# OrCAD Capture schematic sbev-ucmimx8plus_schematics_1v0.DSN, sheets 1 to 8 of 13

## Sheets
1 11. M.2 for WiFi, LEDs: size A3; title: SBEV-UCMIMX8PLUS    11. M.2 for WiFi module; rev: 1.0; note: 8000168001
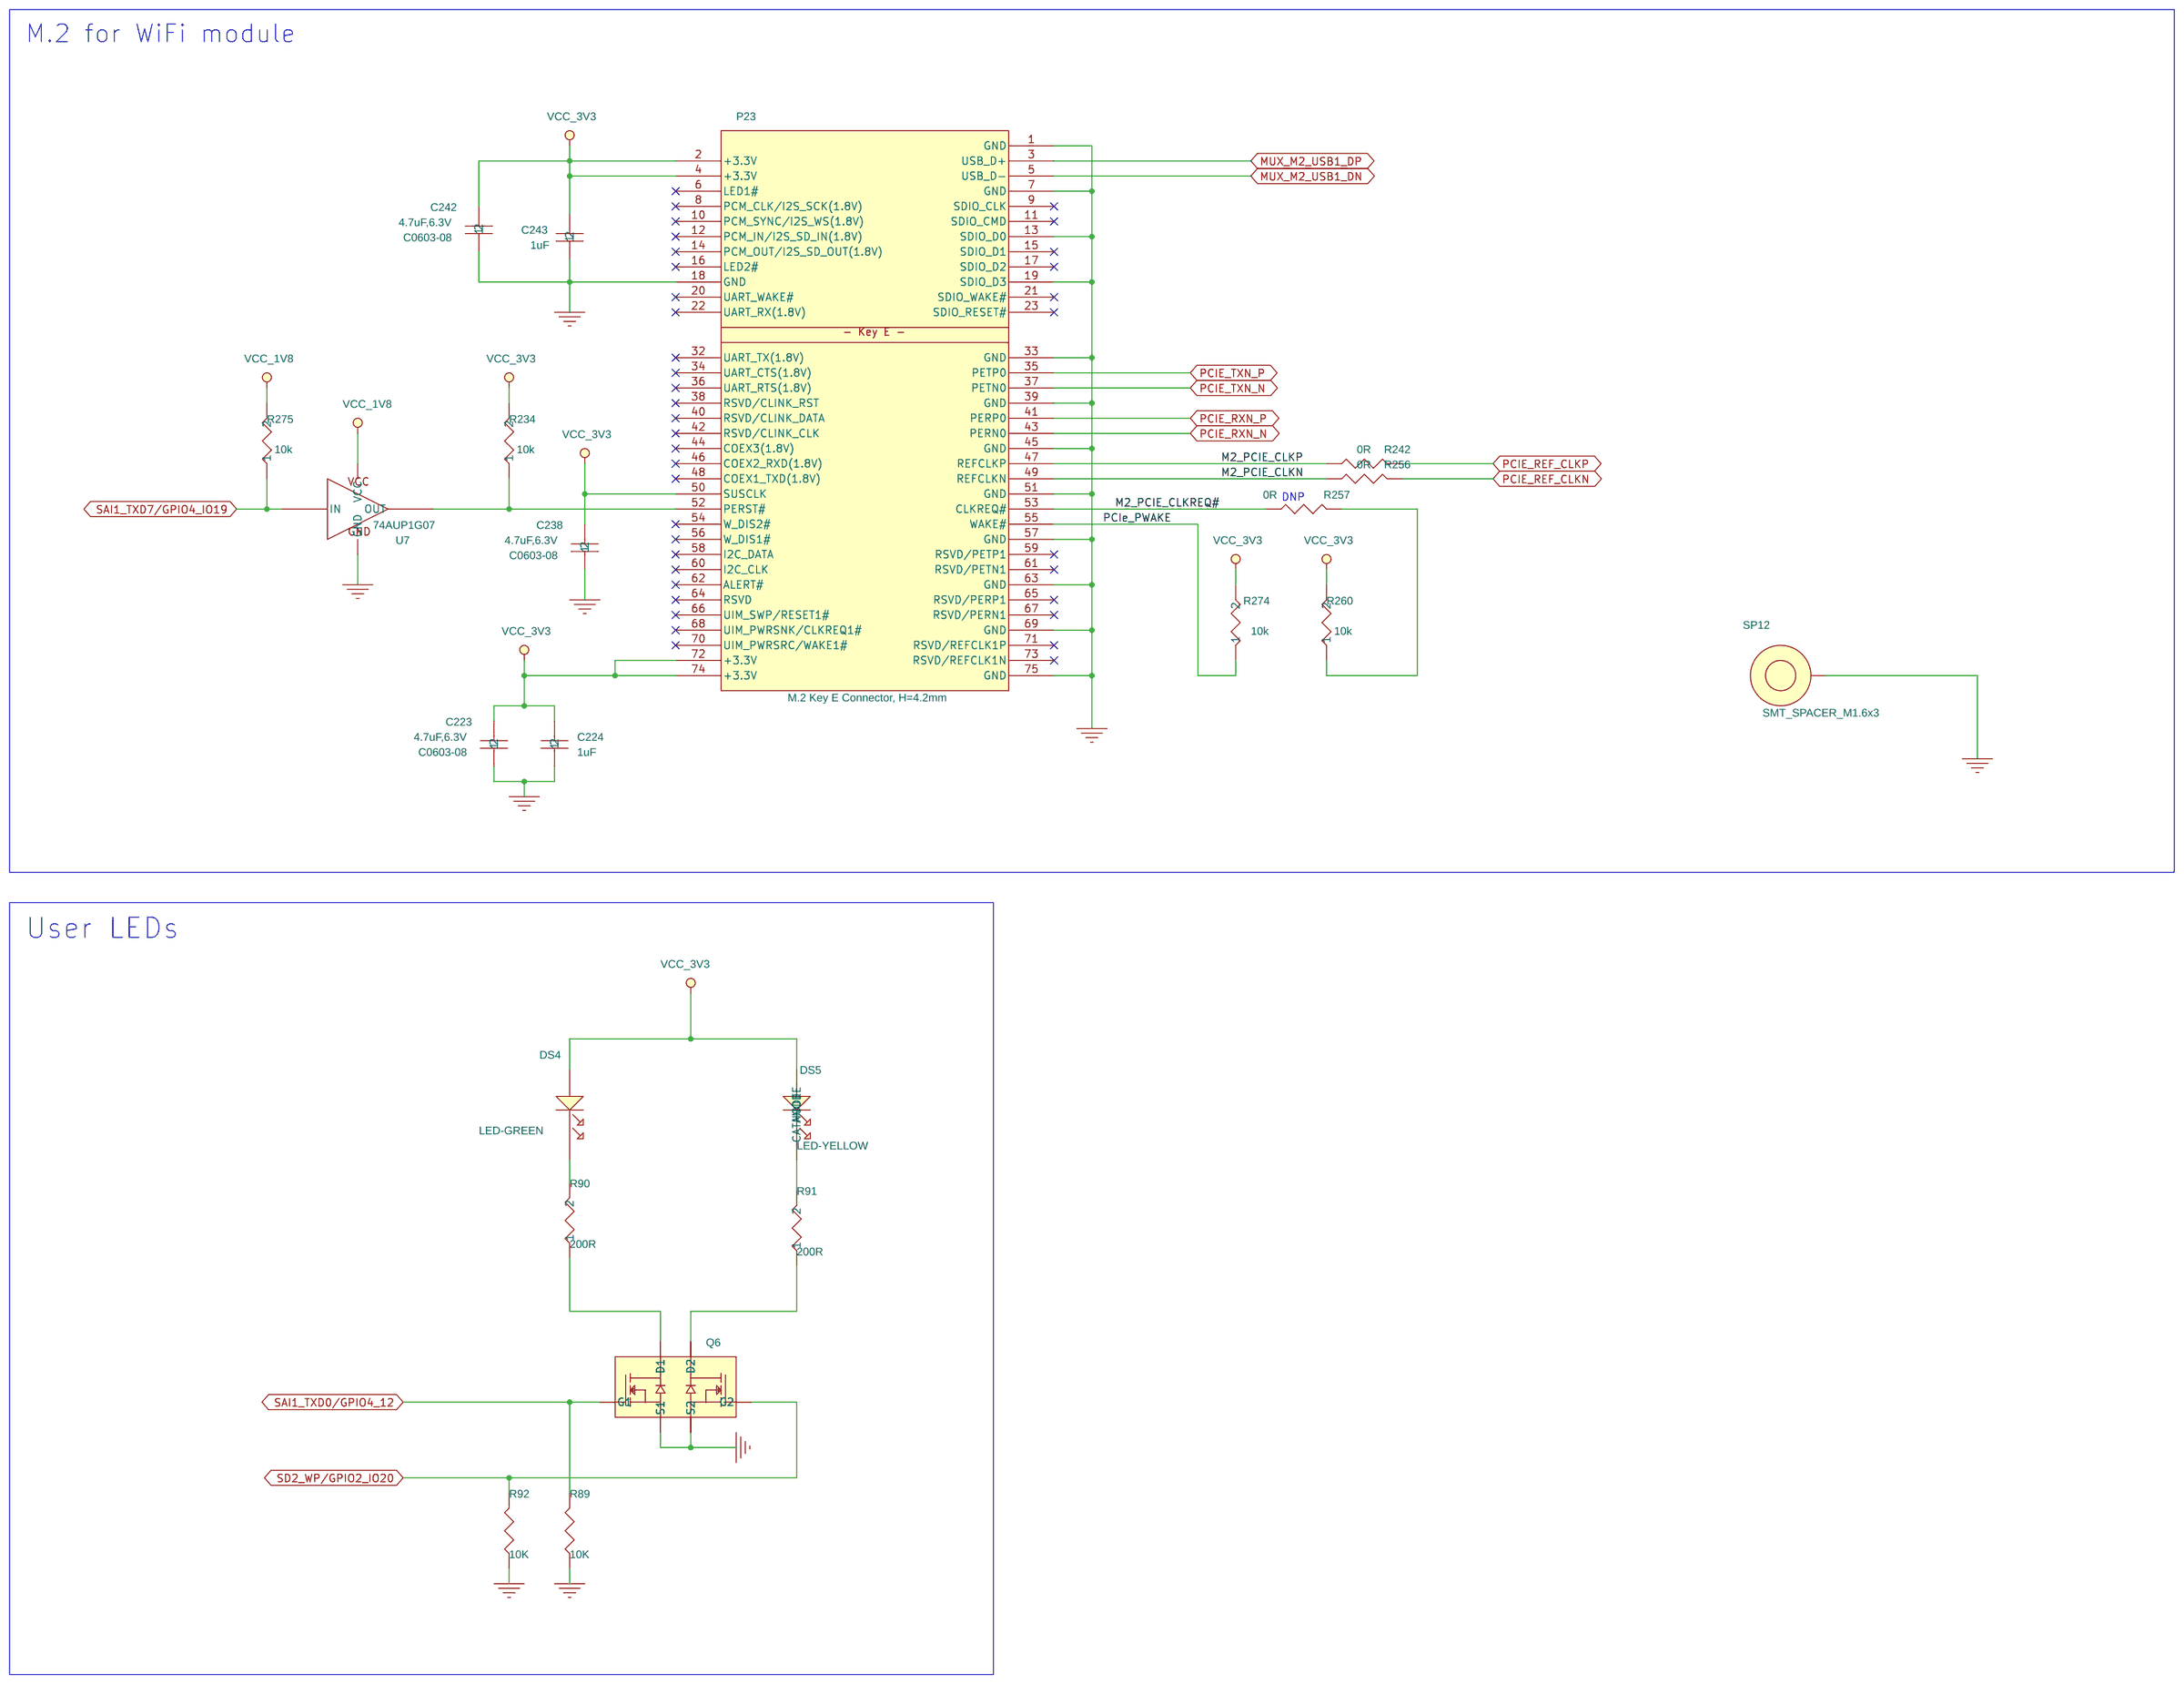
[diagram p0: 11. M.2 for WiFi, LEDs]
2 04. Carrier-board Ethernet: size A3; title: SBEV-UCMIMX8PLUS      04. Secondary Ethernet
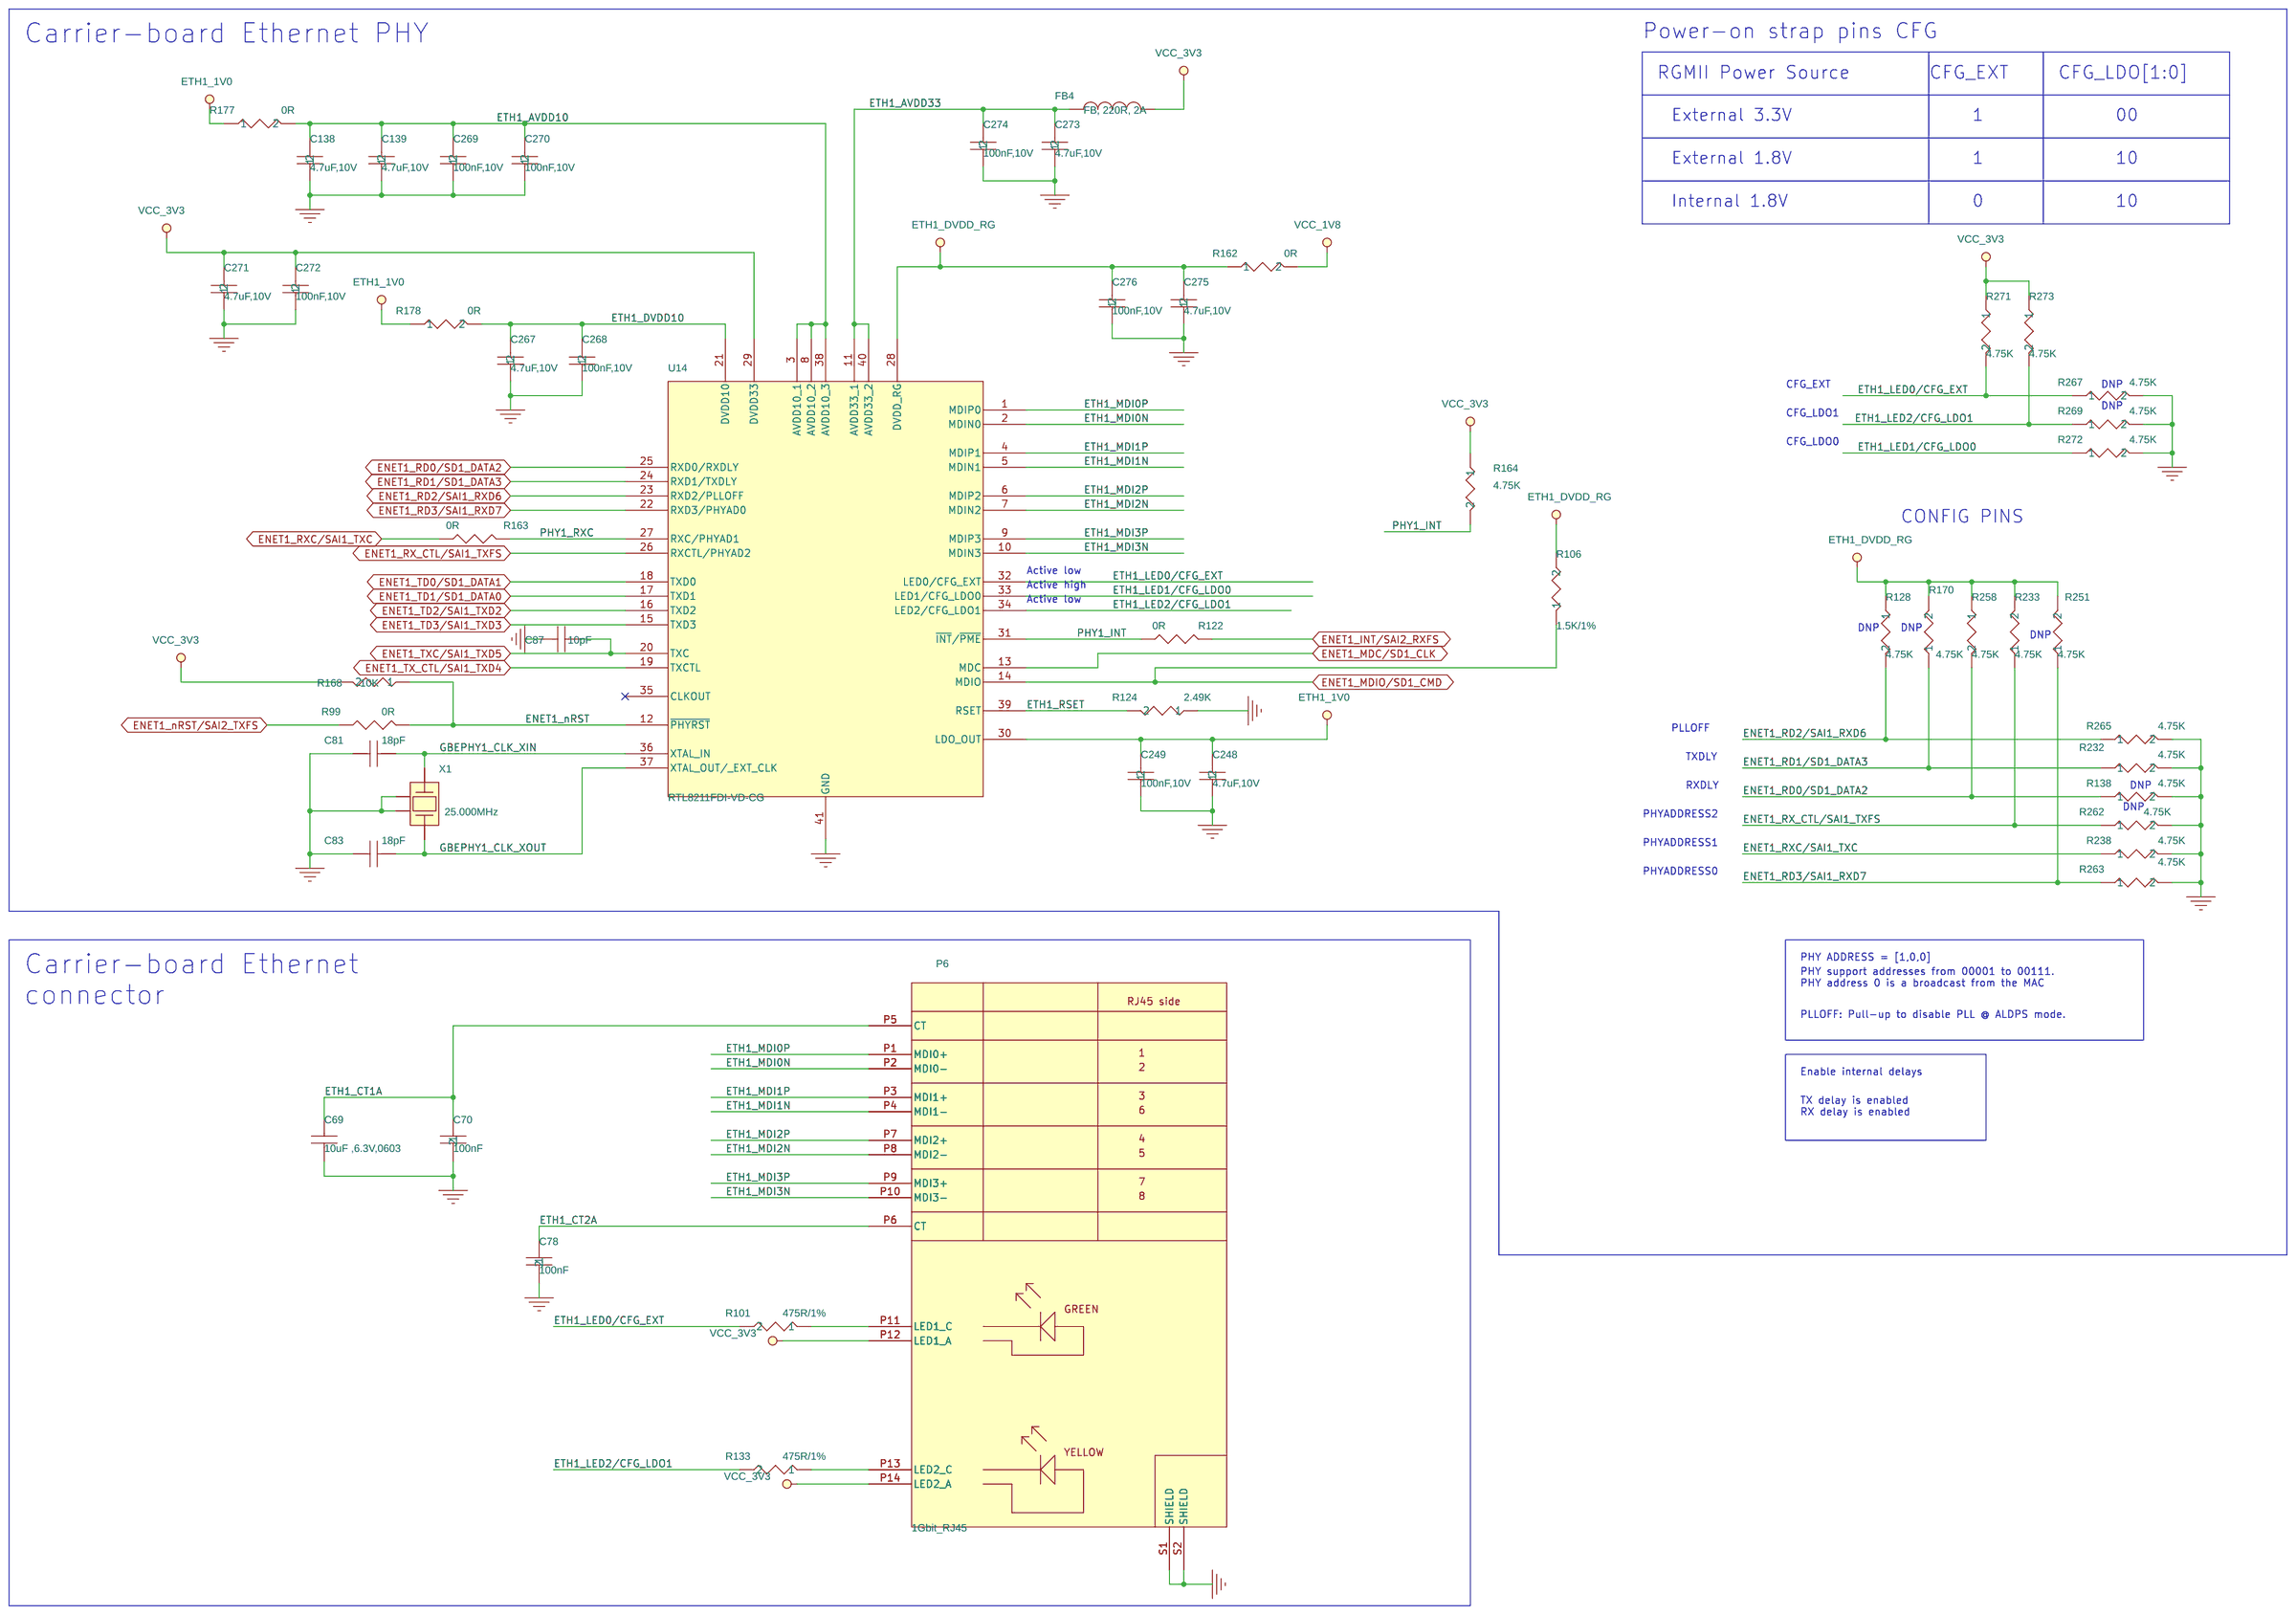
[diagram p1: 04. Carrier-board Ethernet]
3 08. HDMI and MIPI-CSI: size A3; title: SBEV-UCMIMX8PLUS   08. HDMI and MIPI-CSI
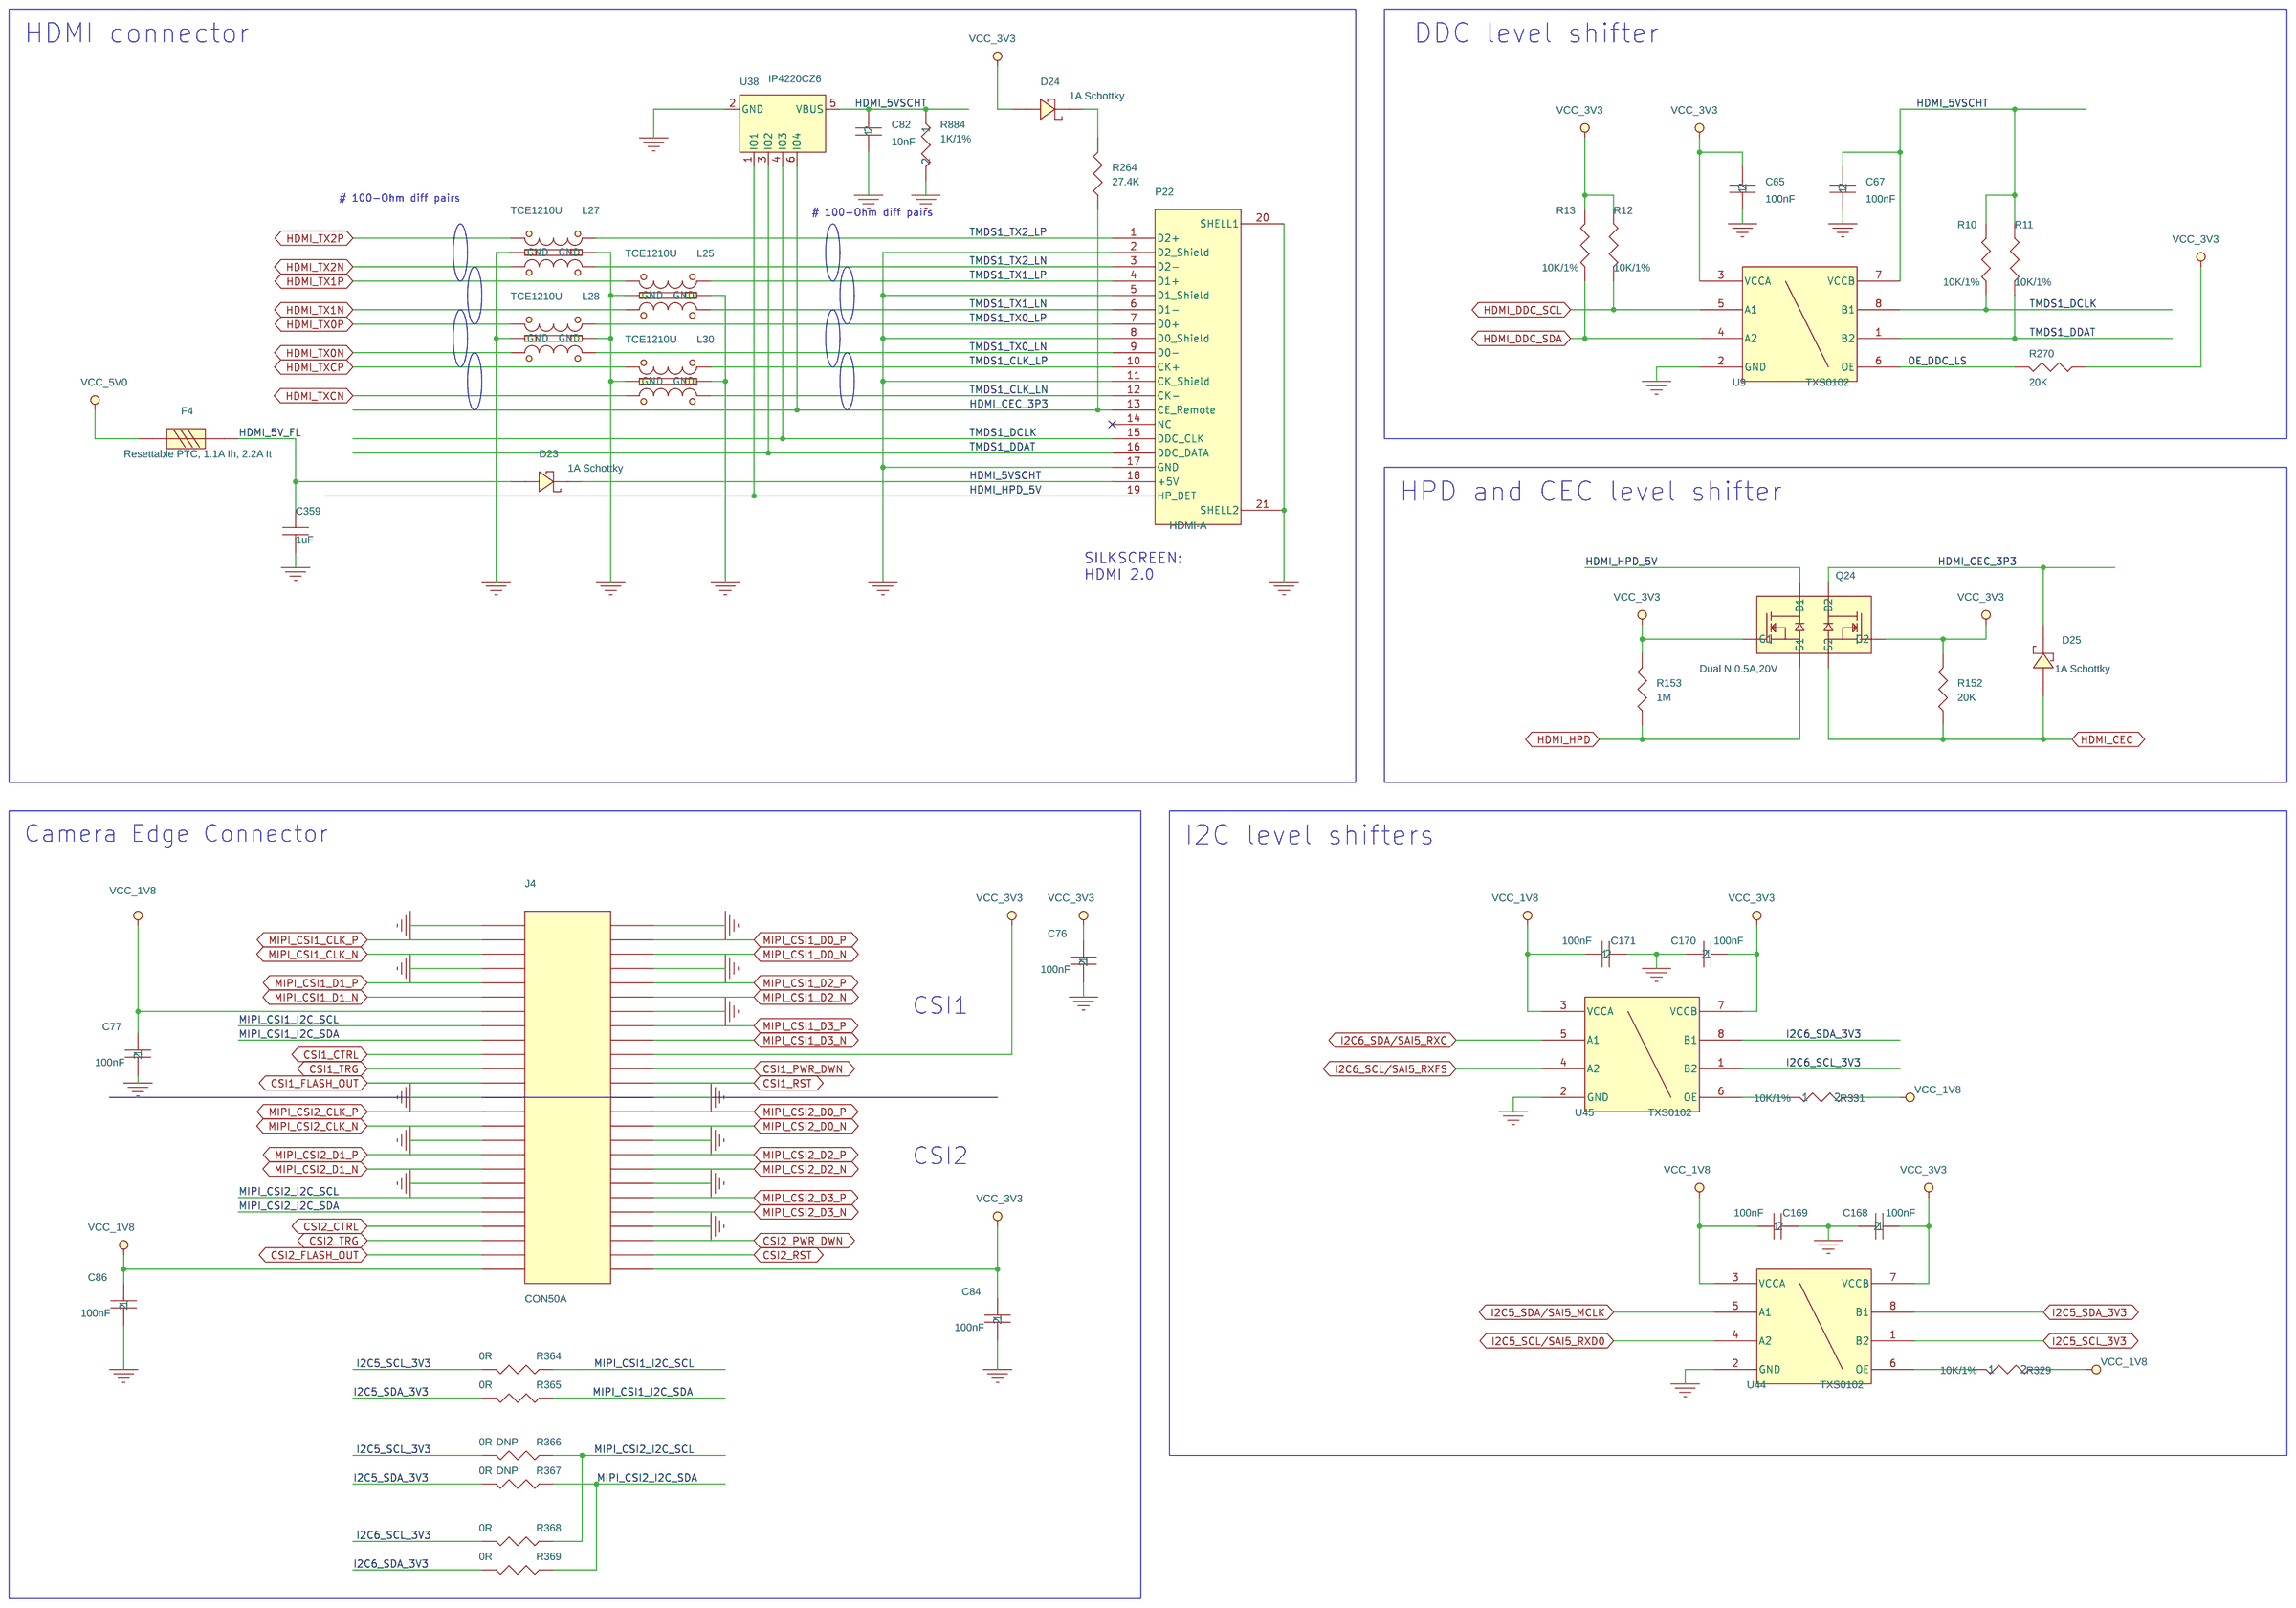
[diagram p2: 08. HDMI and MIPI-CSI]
4 07. LVDS and MIPI-DSI: size A3; title: SBEV-UCMIMX8PLUS   07. LVDS and MPI-DSI
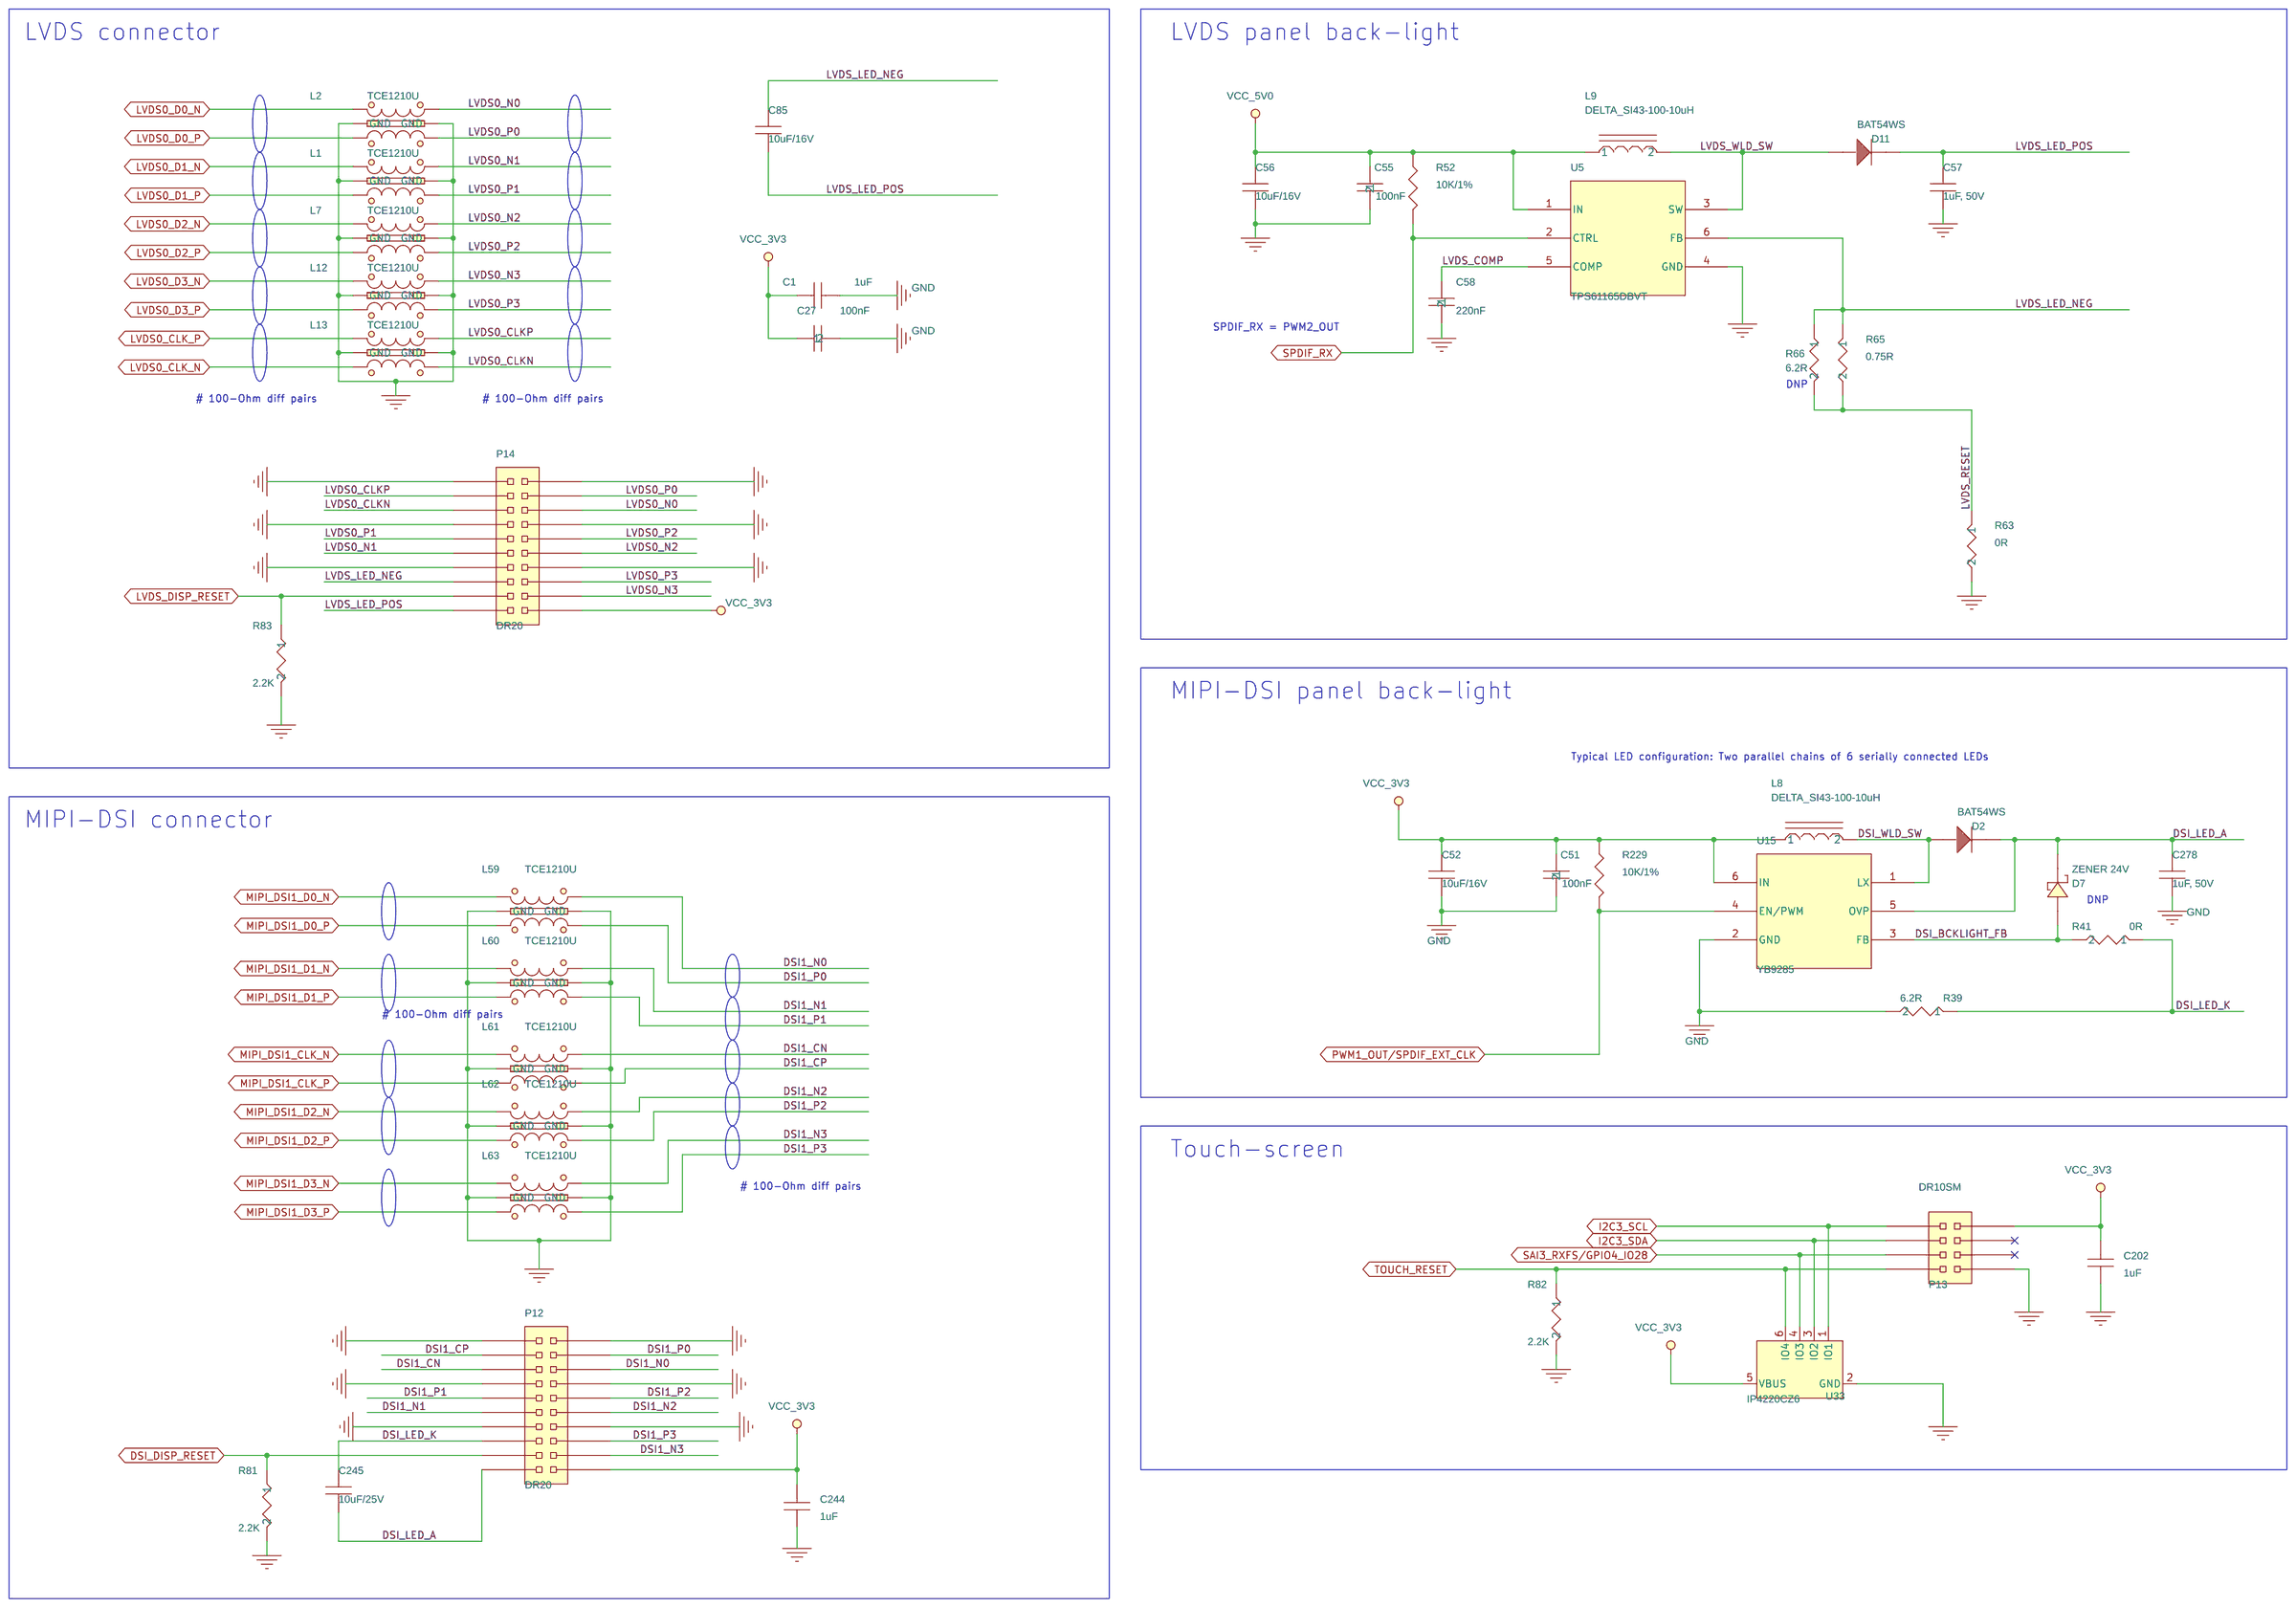
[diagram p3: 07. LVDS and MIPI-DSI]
5 01. Index and Block Diagram: title: SBEV-UCMIMX8PLUS   01. Index and Block Diagram
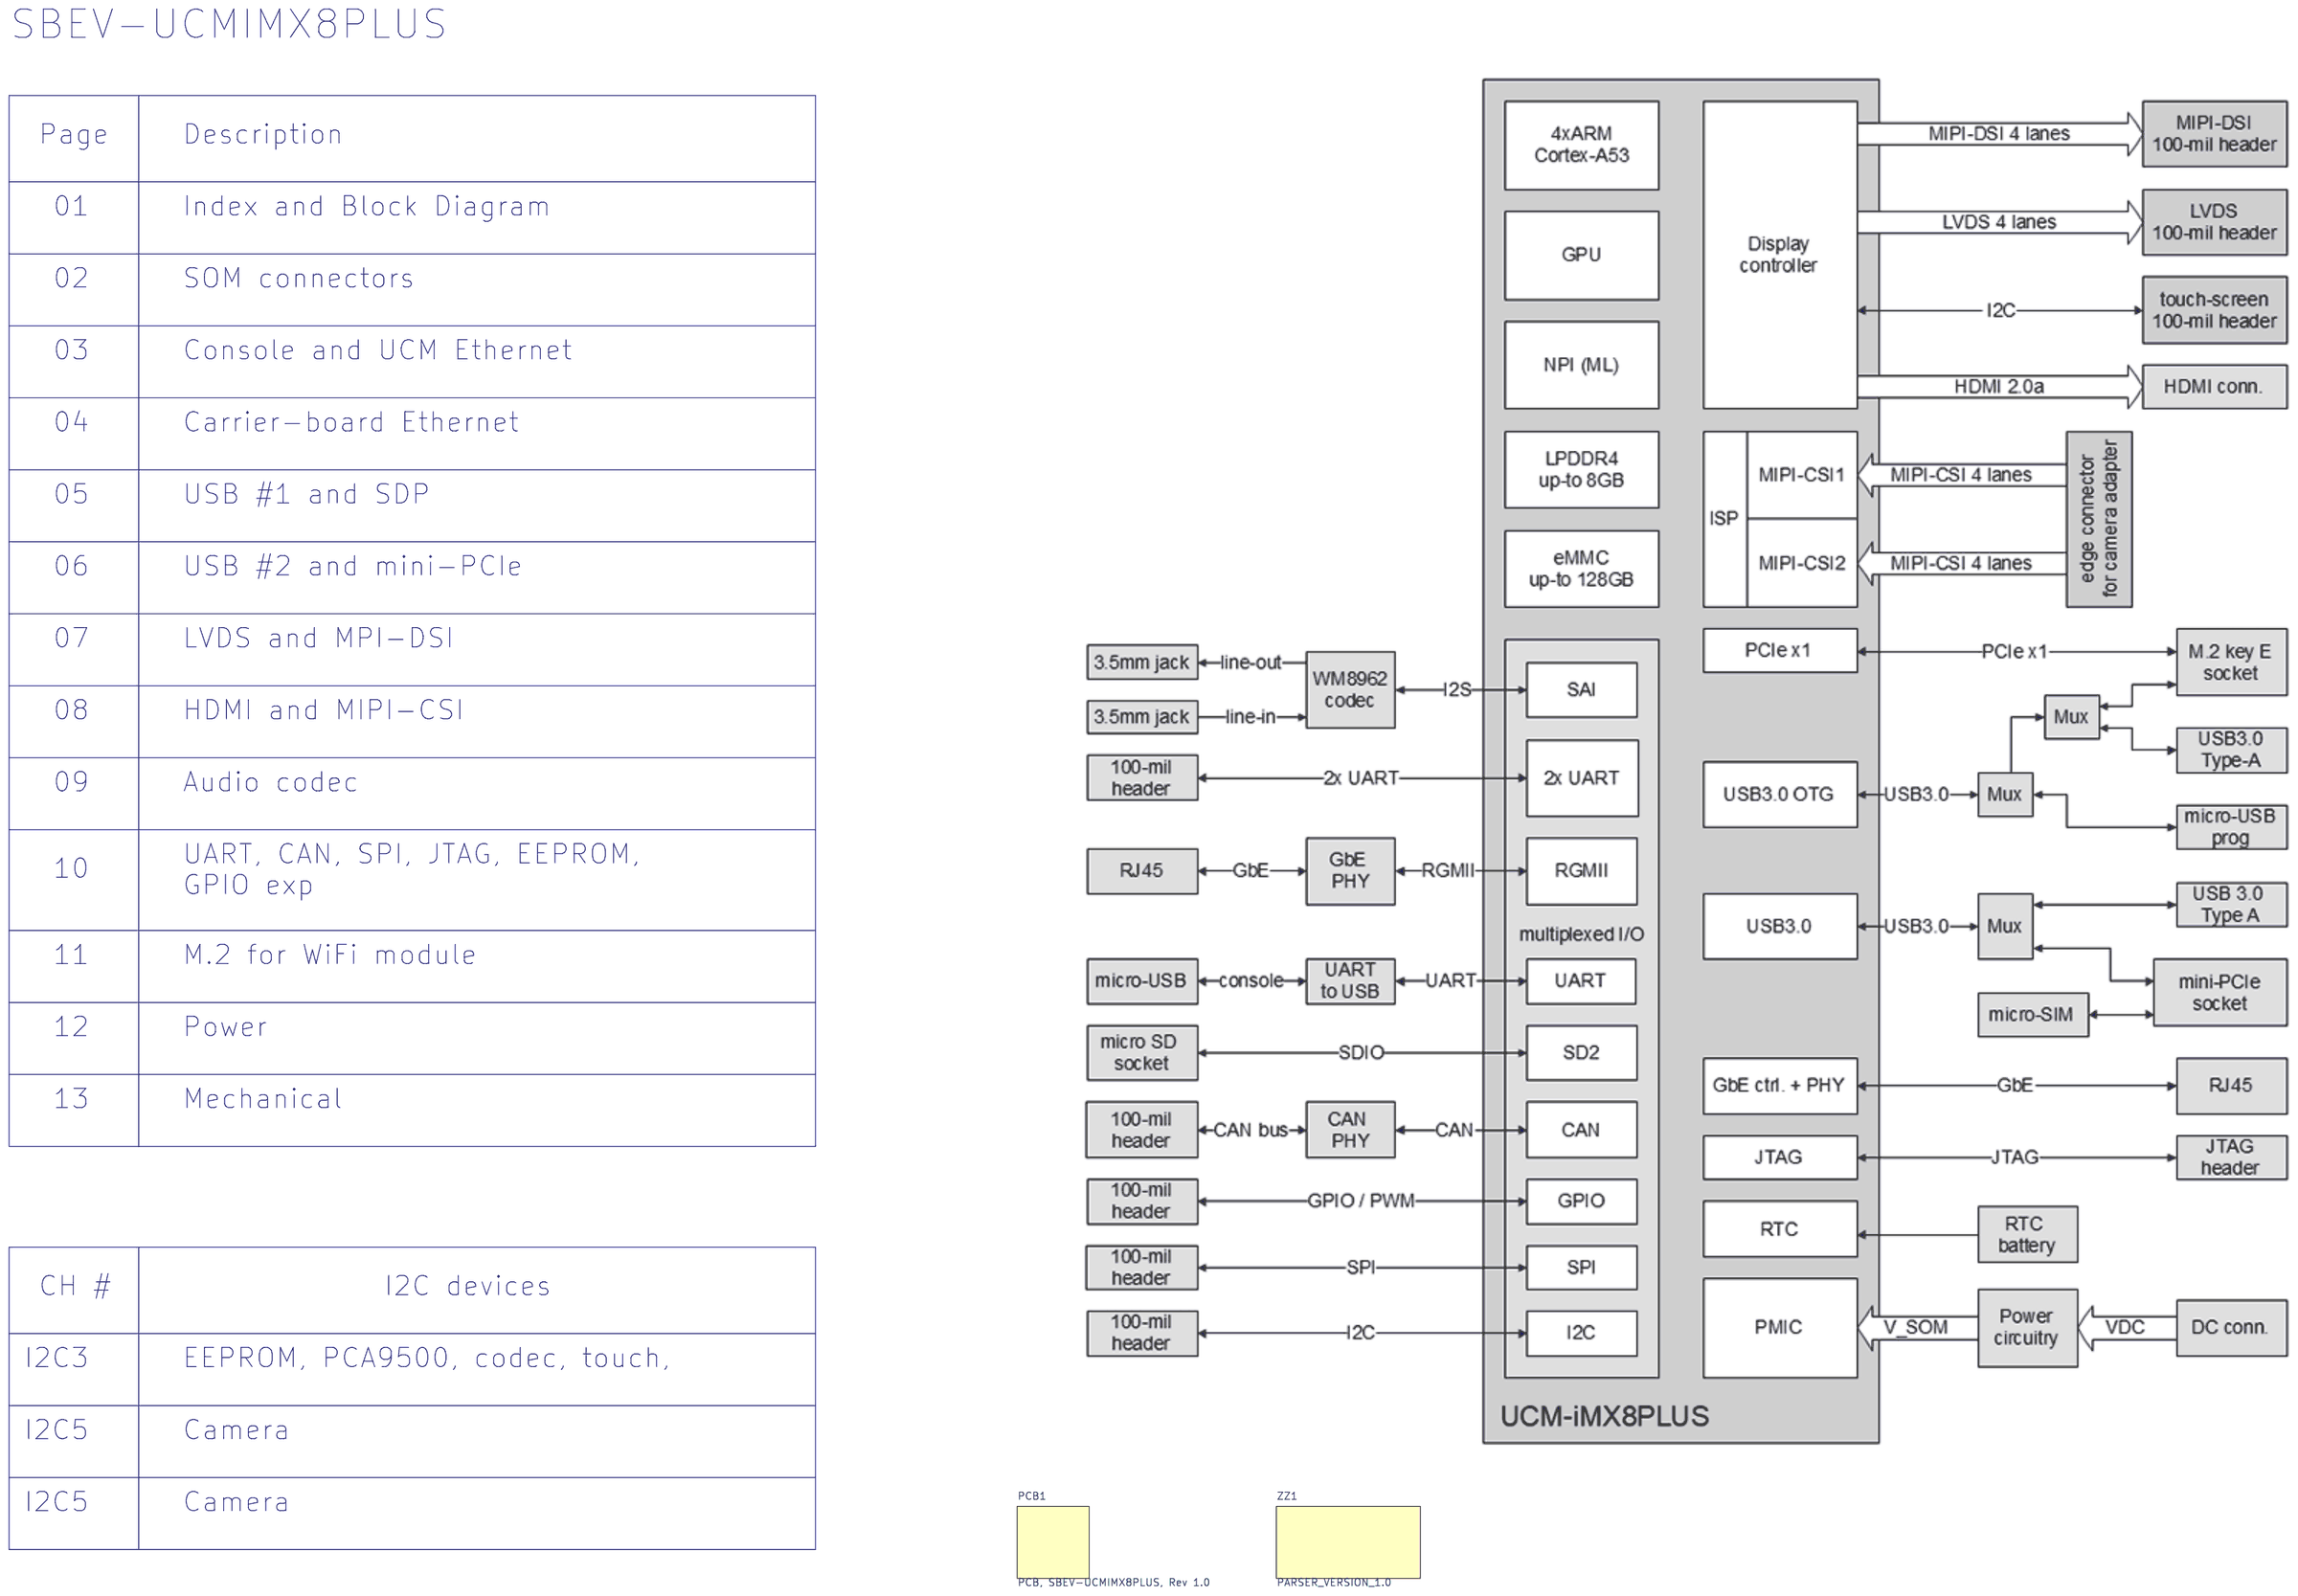
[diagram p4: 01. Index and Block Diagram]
6 02. SOM connectors: size A3; title: SBEV-UCMIMX8PLUS  02. SOM connectors
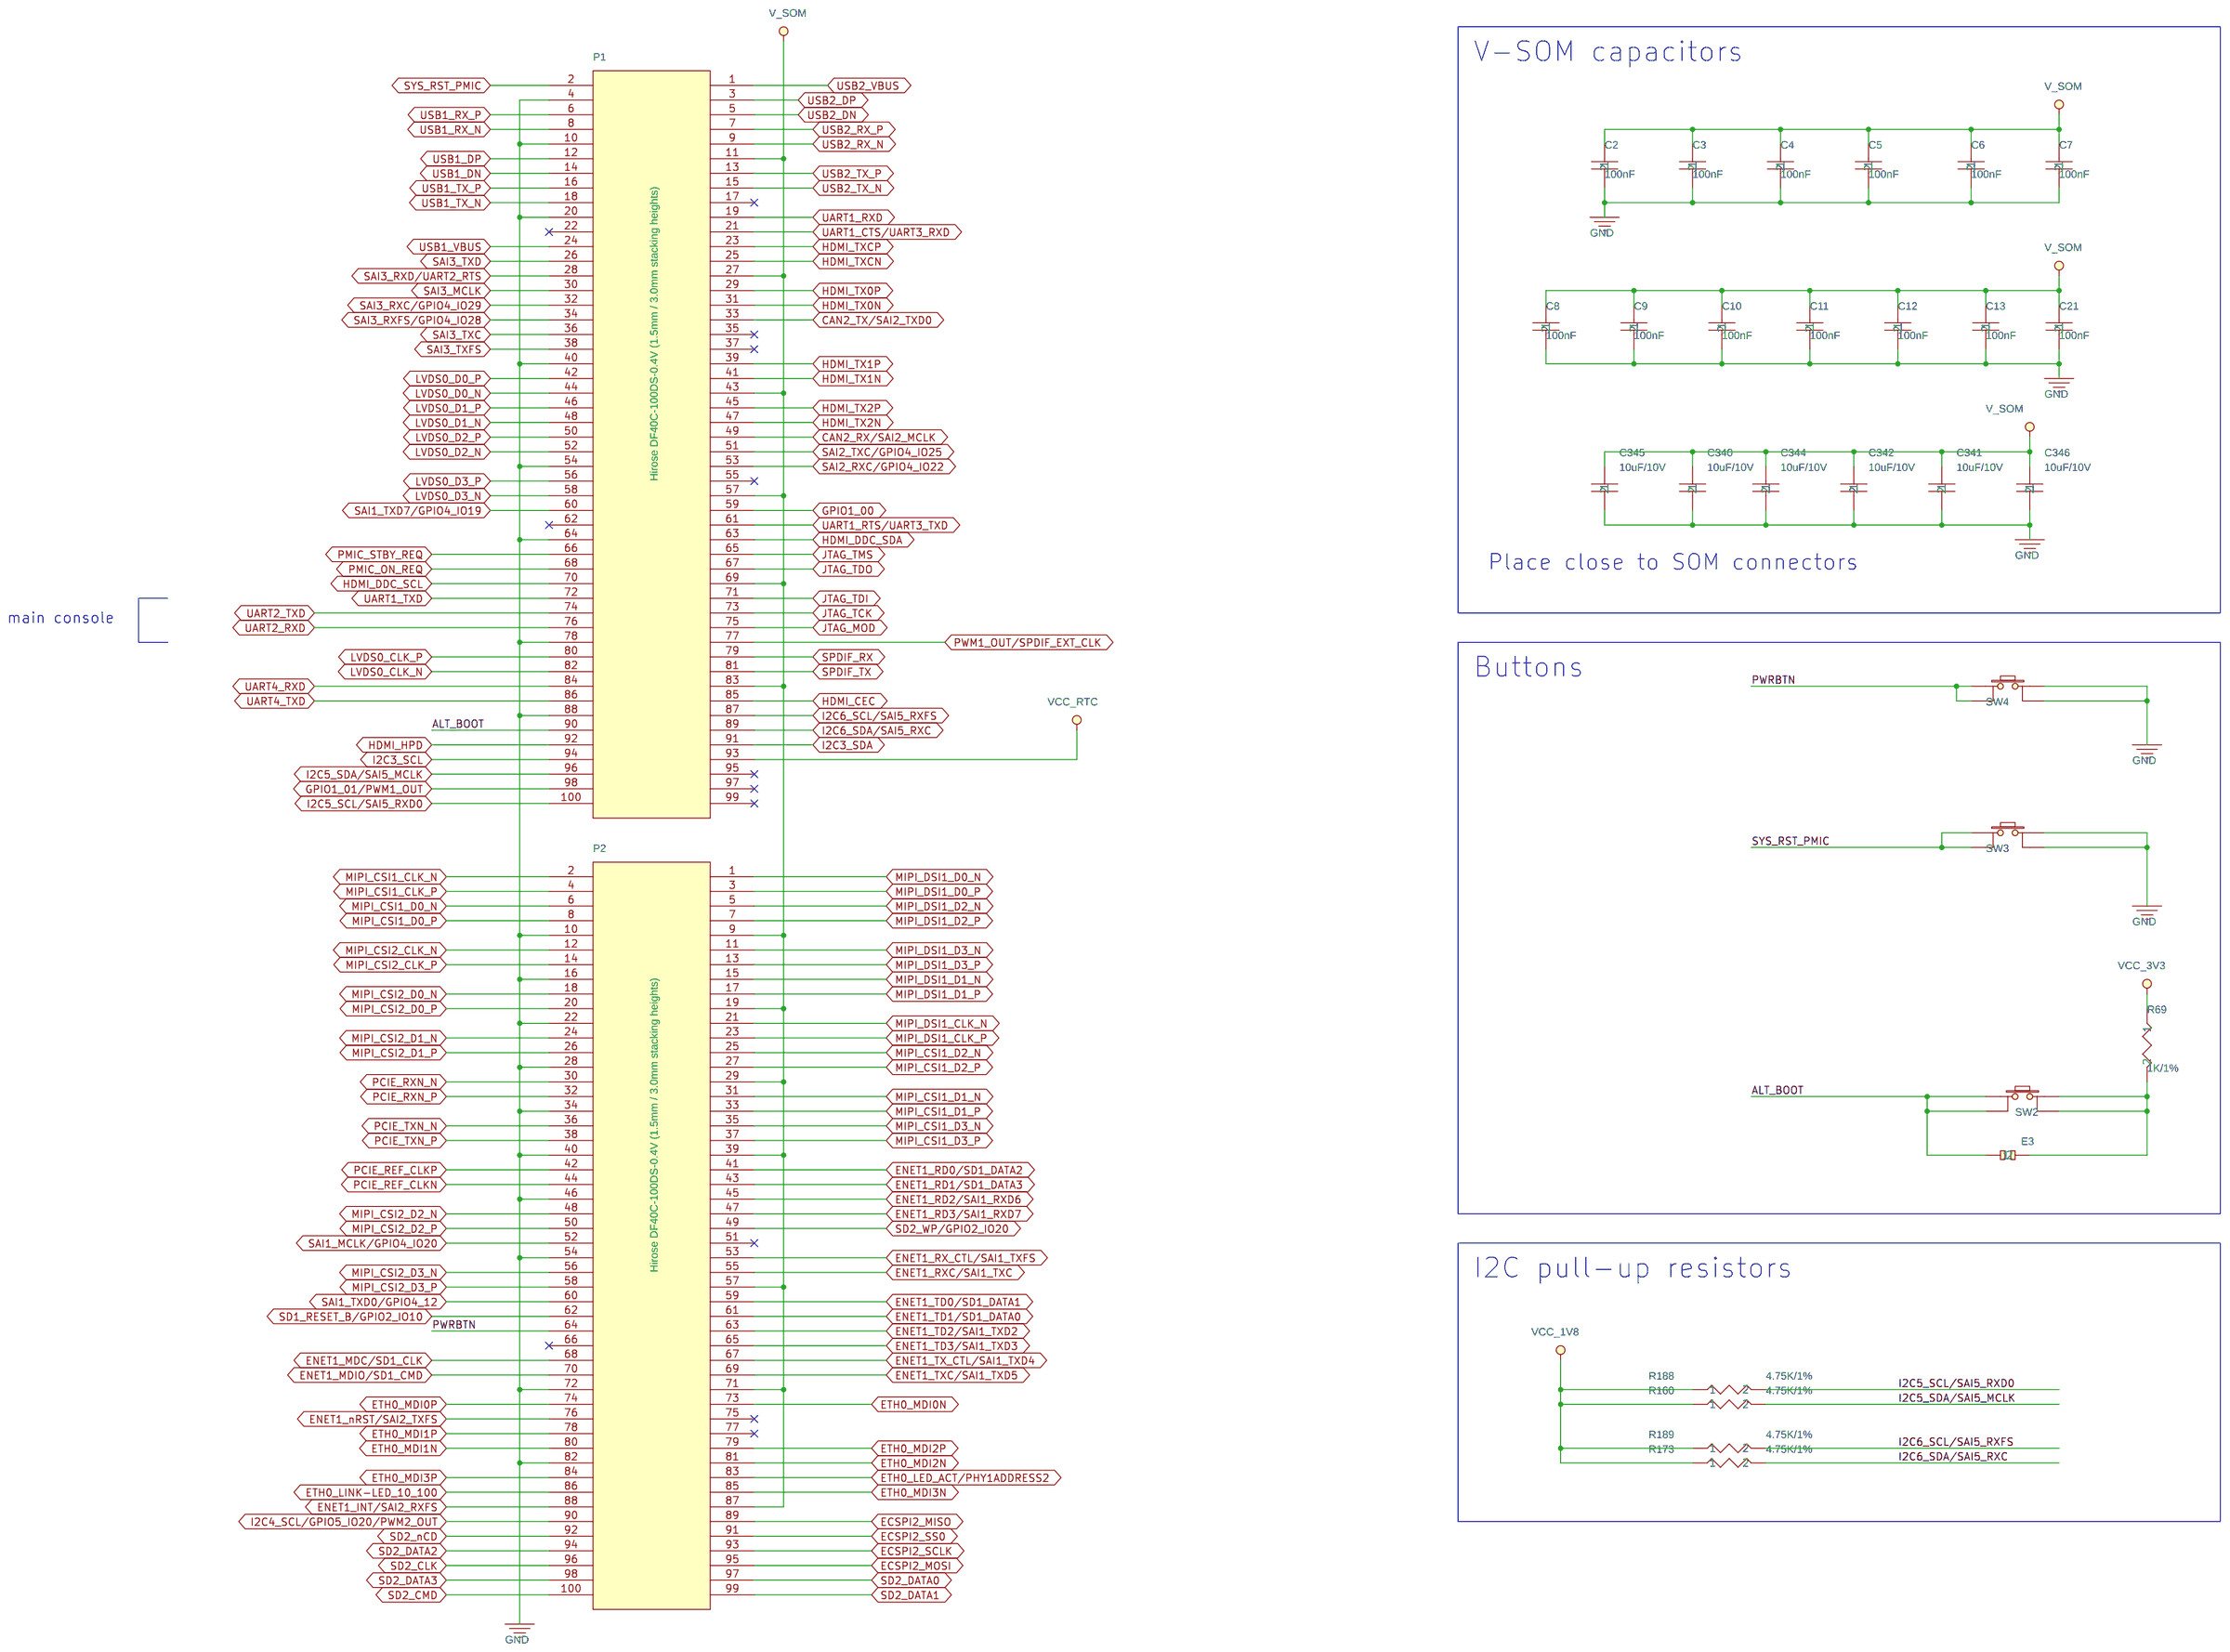
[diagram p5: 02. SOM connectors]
7 03. Console, GbE, micro-SD: size A3; title: SBEV-UCMIMX8PLUS      03. Console, GbE and micro-SD
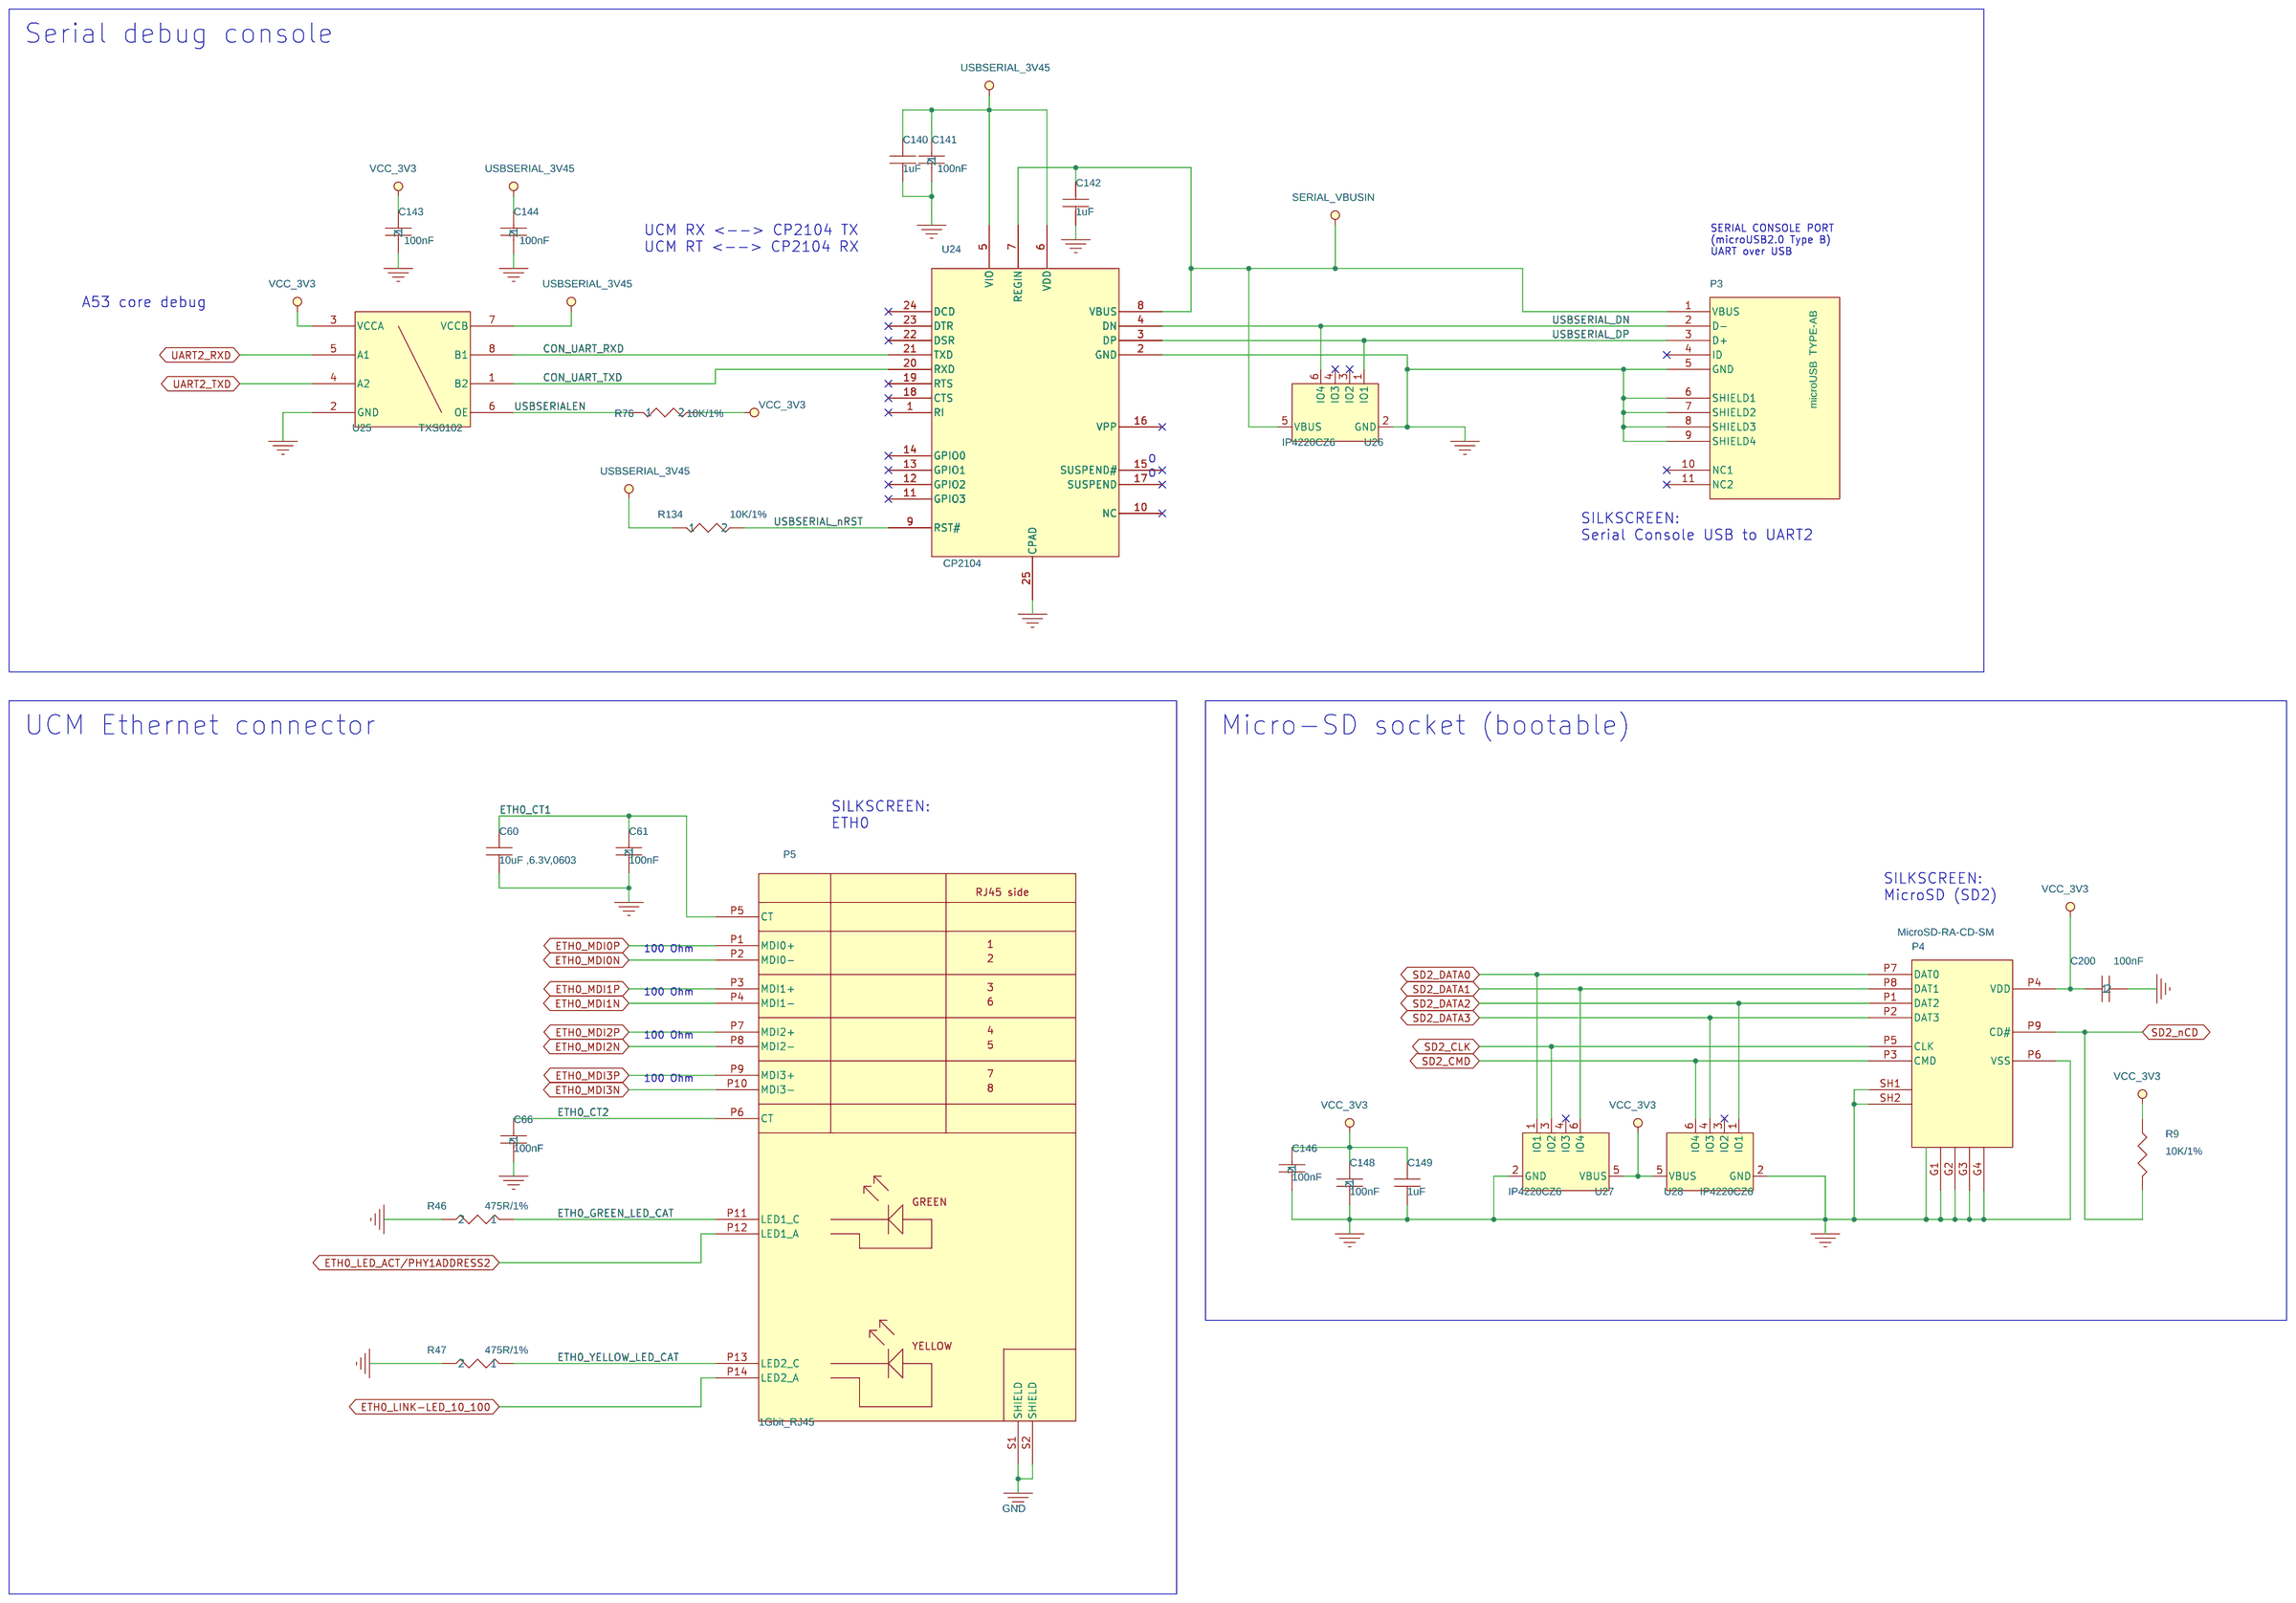
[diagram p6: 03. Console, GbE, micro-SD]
8 05. USB #1 and SDP: size A3; title: SBEV-UCMIMX8PLUS    05. USB #1 and SDP
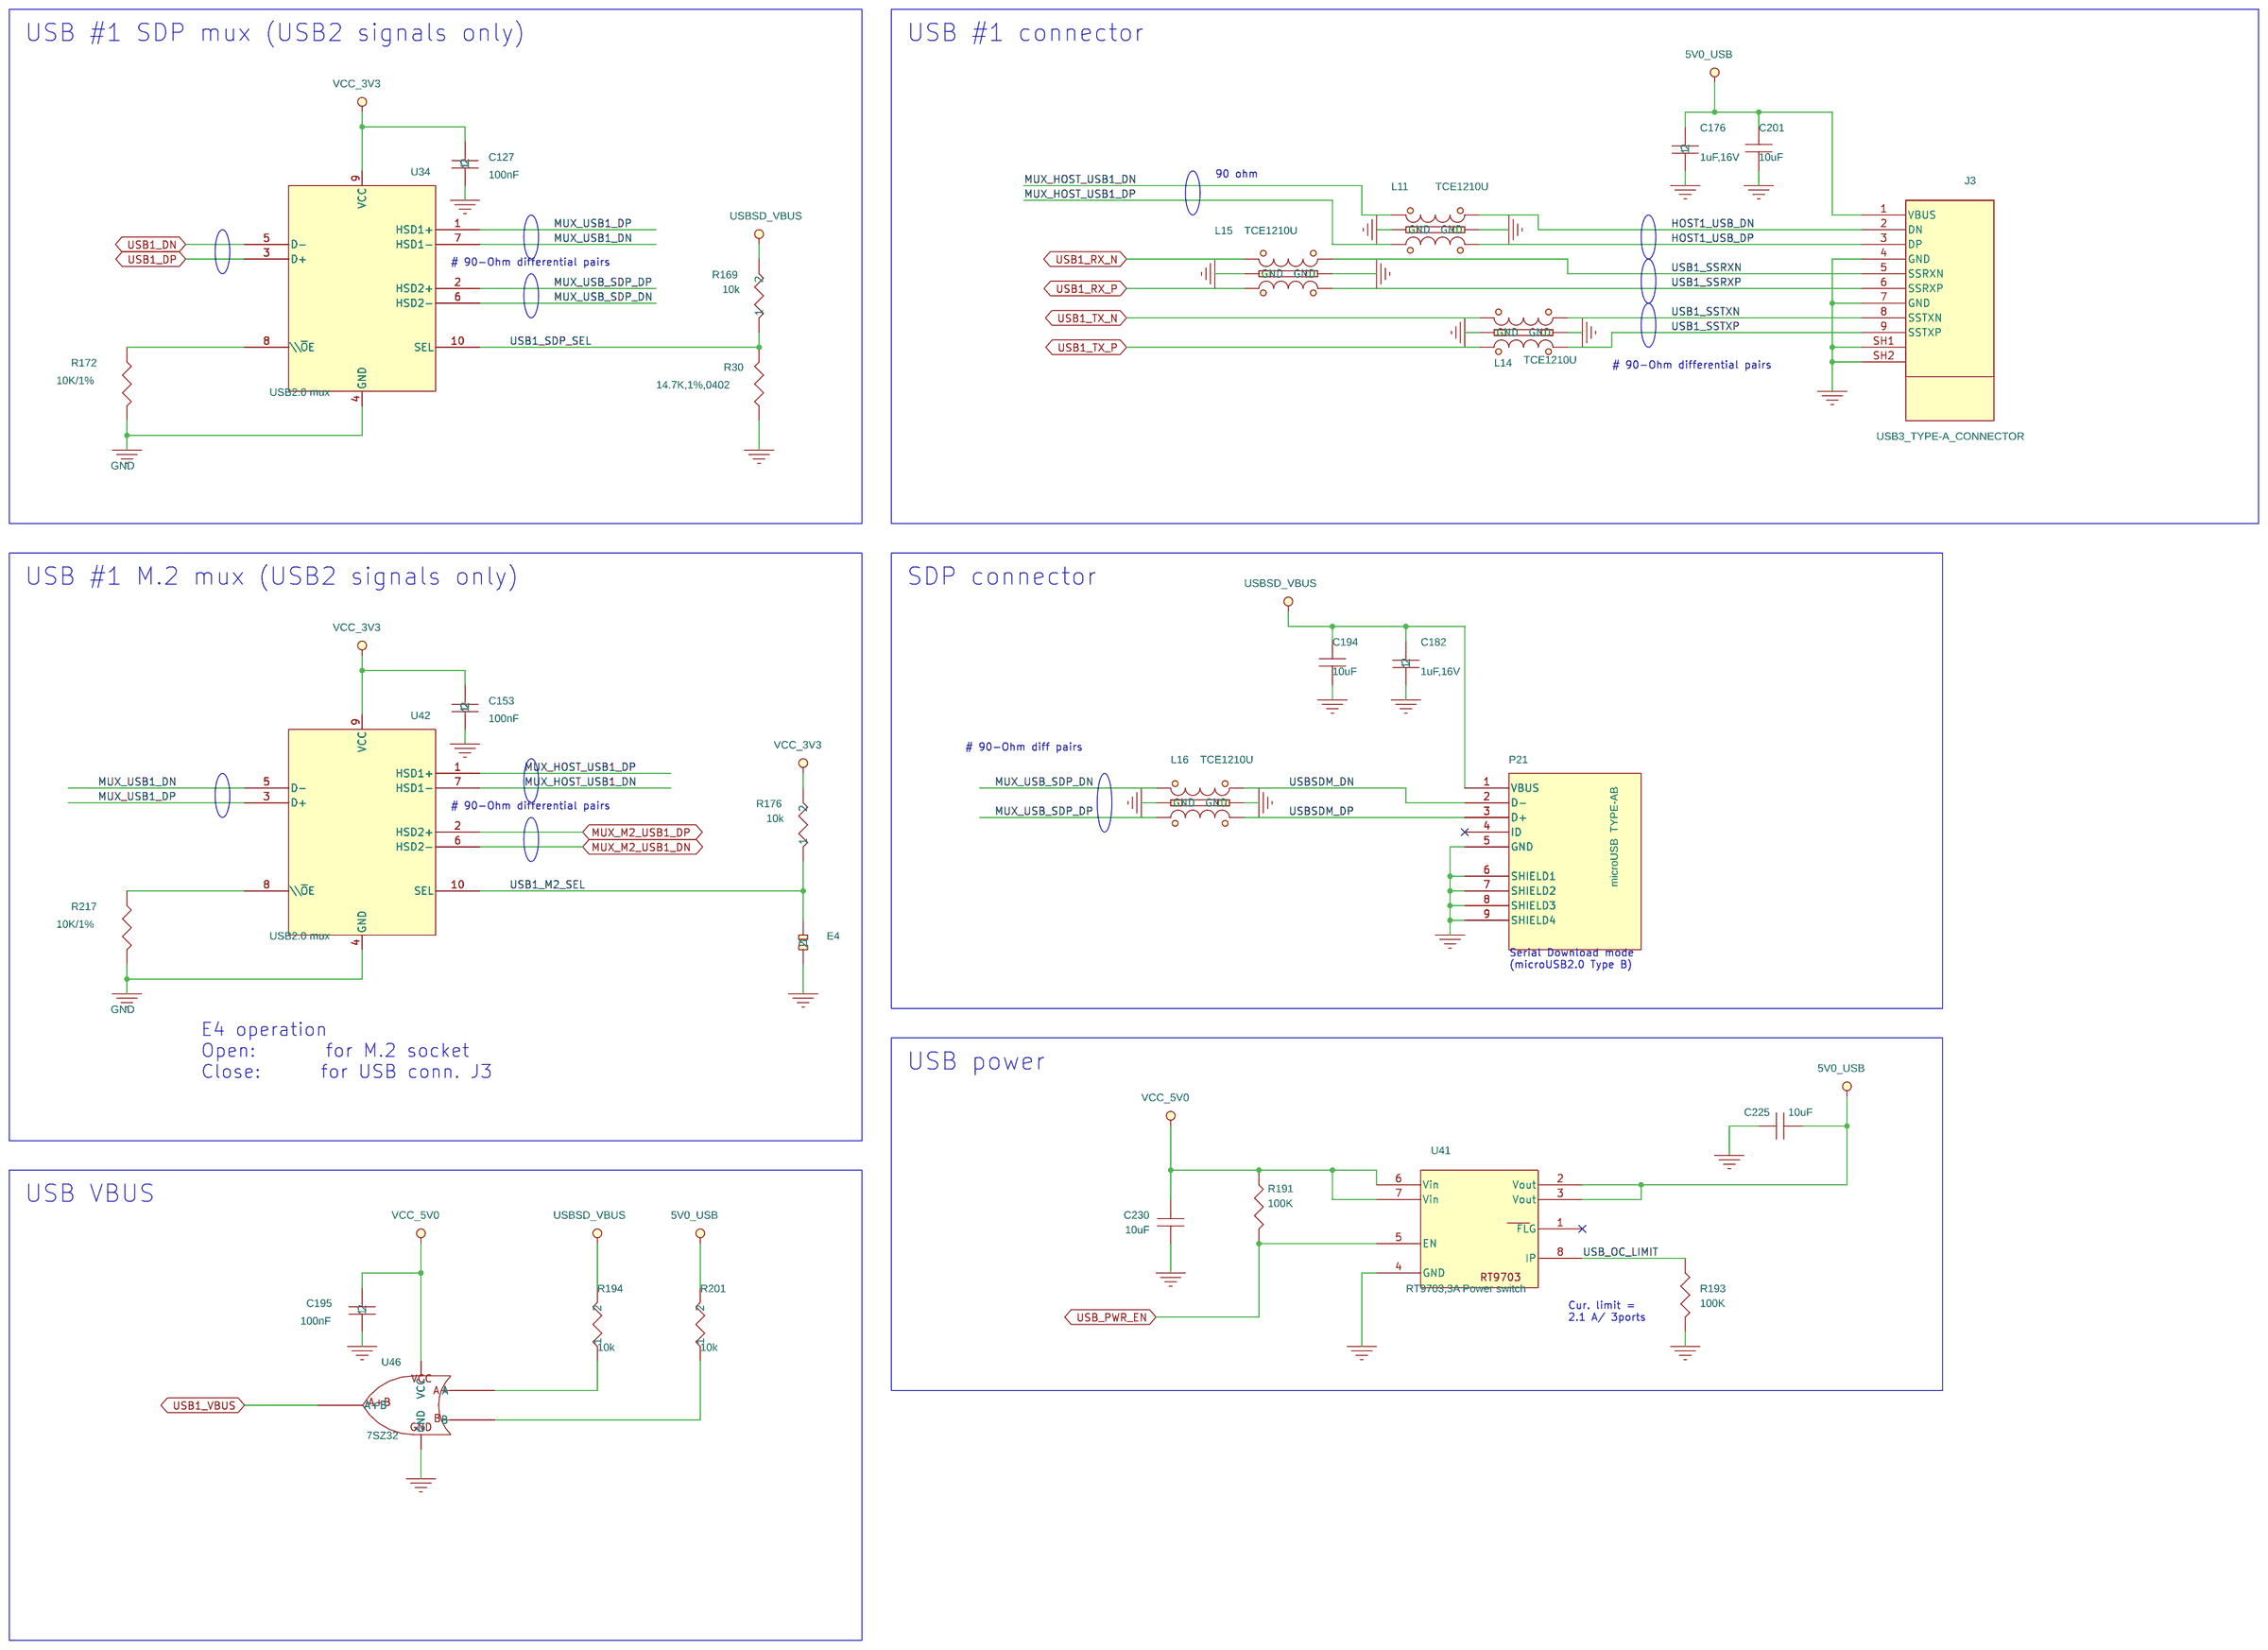
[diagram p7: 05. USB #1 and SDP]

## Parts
sheet 01. Index and Block Diagram
PCB1  PCB, SBEV-UCMIMX8PLUS, Rev 1.0  [PCB]
ZZ1  PARSER_VERSION_1.0
sheet 02. SOM connectors
C2  100nF  [RC0402]
C3  100nF  [RC0402]
C4  100nF  [RC0402]
C5  100nF  [RC0402]
C6  100nF  [RC0402]
C7  100nF  [RC0402]
C8  100nF  [RC0402]
C9  100nF  [RC0402]
C10  100nF  [RC0402]
C11  100nF  [RC0402]
C12  100nF  [RC0402]
C13  100nF  [RC0402]
C21  100nF  [RC0402]
C340  10uF/10V  [RC0402]
C341  10uF/10V  [RC0402]
C342  10uF/10V  [RC0402]
C344  10uF/10V  [RC0402]
C345  10uF/10V  [RC0402]
C346  10uF/10V  [RC0402]
E3  HDR1X2  [1X2THHDR]
P1  Hirose DF40C-100DS-0.4V (1.5mm / 3.0mm stacking heights)  [B2B04M2X50R]
P2  Hirose DF40C-100DS-0.4V (1.5mm / 3.0mm stacking heights)  [B2B04M2X50R]
R69  1K/1%  [RC0402]
R160  4.75K/1%  [RC0402]
R173  4.75K/1%  [RC0402]
R188  4.75K/1%  [RC0402]
R189  4.75K/1%  [RC0402]
SW2  PushB  [TACTSW6x6SM]
SW3  PushB  [TACTSW6x6SM]
SW4  PushB  [TACTSW6x6SM]
sheet 03. Console, GbE, micro-SD
C60  10uF ,6.3V,0603  [RC0603]
C61  100nF  [RC0402]
C66  100nF  [RC0402]
C140  1uF  [RC0402]
C141  100nF  [RC0402]
C142  1uF  [RC0402]
C143  100nF  [RC0402]
C144  100nF  [RC0402]
C146  100nF  [RC0402]
C148  100nF  [RC0402]
C149  1uF  [RC0402]
C200  100nF  [RC0402]
P3  microUSB  TYPE-AB  [MICRO-USB-AB-RA-SM]
P4  MicroSD-RA-CD-SM  [MicroSD-RA-CD-SM]
P5  1Gbit_RJ45  [DUSBRJ-1G]
R9  10K/1%  [RC0402]
R46  475R/1%  [RC0402]
R47  475R/1%  [RC0402]
R76  10K/1%  [RC0402]
R134  10K/1%  [RC0402]
U24  CP2104  [MO-220VGGD-8]
U25  TXS0102  [MO-187DA-8]
U26  IP4220CZ6  [SOT23-6L]
U27  IP4220CZ6  [SOT23-6L]
U28  IP4220CZ6  [SOT23-6L]
sheet 04. Carrier-board Ethernet
C69  10uF ,6.3V,0603  [RC0603]
C70  100nF  [RC0402]
C78  100nF  [RC0402]
C81  18pF  [RC0402]
C83  18pF  [RC0402]
C87  10pF  [RC0402]
C138  4.7uF,10V  [RC0402]
C139  4.7uF,10V  [RC0402]
C248  4.7uF,10V  [RC0402]
C249  100nF,10V  [RC0402]
C267  4.7uF,10V  [RC0402]
C268  100nF,10V  [RC0402]
C269  100nF,10V  [RC0402]
C270  100nF,10V  [RC0402]
C271  4.7uF,10V  [RC0402]
C272  100nF,10V  [RC0402]
C273  4.7uF,10V  [RC0402]
C274  100nF,10V  [RC0402]
C275  4.7uF,10V  [RC0402]
C276  100nF,10V  [RC0402]
FB4  FB, 220R, 2A  [FB0402]
P6  1Gbit_RJ45  [DUSBRJ-1G]
R99  0R  [RC0402]
R101  475R/1%  [RC0402]
R106  1.5K/1%  [RC0402]
R122  0R  [RC0402]
R124  2.49K  [RC0402]
R128  4.75K  [RC0402]
R133  475R/1%  [RC0402]
R138  4.75K  [RC0402]
R162  0R  [RC0402]
R163  0R  [RC0402]
R164  4.75K  [RC0402]
R168  10K  [RC0402]
R170  4.75K  [RC0402]
R177  0R  [RC0402]
R178  0R  [RC0402]
R232  4.75K  [RC0402]
R233  4.75K  [RC0402]
R238  4.75K  [RC0402]
R251  4.75K  [RC0402]
R258  4.75K  [RC0402]
R262  4.75K  [RC0402]
R263  4.75K  [RC0402]
R265  4.75K  [RC0402]
R267  4.75K  [RC0402]
R269  4.75K  [RC0402]
R271  4.75K  [RC0402]
R272  4.75K  [RC0402]
R273  4.75K  [RC0402]
U14  RTL8211FDI-VD-CG  [qfn40_0p4_5x5mm]
X1  25.000MHz  [OSC3225]
sheet 05. USB #1 and SDP
C127  100nF  [RC0402]
C153  100nF  [RC0402]
C176  1uF,16V  [RC0402]
C182  1uF,16V  [RC0402]
C194  10uF  [C0603-08]
C195  100nF  [RC0402]
C201  10uF  [C0603-08]
C225  10uF  [C0603-08]
C230  10uF  [C0603-08]
E4  HDR1X2  [1X2THHDR]
J3  USB3_TYPE-A_CONNECTOR  [USB3_TYPEA]
L11  TCE1210U  [EMI1012-ESD]
L14  TCE1210U  [EMI1012-ESD]
L15  TCE1210U  [EMI1012-ESD]
L16  TCE1210U  [EMI1012-ESD]
P21  microUSB  TYPE-AB  [MICRO-USB-AB-RA-SM]
R30  14.7K,1%,0402  [RC0402]
R169  10k  [RC0402]
R172  10K/1%  [RC0402]
R176  10k  [RC0402]
R191  100K  [RC0402]
R193  100K  [RC0402]
R194  10k  [RC0402]
R201  10k  [RC0402]
R217  10K/1%  [RC0402]
U34  USB2.0 mux  [MO-255U1418E]
U41  RT9703,3A Power switch  [SO-8-150]
U42  USB2.0 mux  [MO-255U1418E]
U46  7SZ32  [SC70]
sheet 07. LVDS and MIPI-DSI
C1  1uF  [RC0402]
C27  100nF  [RC0402]
C51  100nF  [RC0402]
C52  10uF/16V  [RC0603]
C55  100nF  [RC0402]
C56  10uF/16V  [RC0603]
C57  1uF, 50V  [RC0603]
C58  220nF  [RC0402]
C85  10uF/16V  [RC0603]
C202  1uF  [RC0402]
C244  1uF  [RC0402]
C245  10uF/25V  [RC0603]
C278  1uF, 50V  [RC0603]
D2  BAT54WS  [SOD-323]
D7  ZENER 24V  [SOD-123]
D11  BAT54WS  [SOD-323]
L1  TCE1210U  [EMI1012-ESD]
L2  TCE1210U  [EMI1012-ESD]
L7  TCE1210U  [EMI1012-ESD]
L8  DELTA_SI43-100-10uH  [IND4x4x2_5]
L9  DELTA_SI43-100-10uH  [IND4x4x2_5]
L12  TCE1210U  [EMI1012-ESD]
L13  TCE1210U  [EMI1012-ESD]
L59  TCE1210U  [EMI1012-ESD]
L60  TCE1210U  [EMI1012-ESD]
L61  TCE1210U  [EMI1012-ESD]
L62  TCE1210U  [EMI1012-ESD]
L63  TCE1210U  [EMI1012-ESD]
P12  DR20  [2X12THHDR]
P13  DR10SM  [2X4SMHDR]
P14  DR20  [2X12THHDR]
R39  6.2R  [RC0402]
R41  0R  [RC0402]
R52  10K/1%  [RC0402]
R63  0R  [RC0402]
R65  0.75R  [RC0402]
R66  6.2R  [RC0402]
R81  2.2K  [RC0402]
R82  2.2K  [RC0402]
R83  2.2K  [RC0402]
R229  10K/1%  [RC0402]
U5  TPS61165DBVT  [SOT23-6]
U15  YB9285  [SOT23-6L]
U33  IP4220CZ6  [SOT23-6L]
sheet 08. HDMI and MIPI-CSI
C65  100nF  [RC0402]
C67  100nF  [RC0402]
C76  100nF  [RC0402]
C77  100nF  [RC0402]
C82  10nF  [RC0402]
C84  100nF  [RC0402]
C86  100nF  [RC0402]
C168  100nF  [RC0402]
C169  100nF  [RC0402]
C170  100nF  [RC0402]
C171  100nF  [RC0402]
C359  1uF  [RC0402]
D23  1A Schottky  [SOD-123]
D24  1A Schottky  [SOD-123]
D25  1A Schottky  [SOD-123]
F4  Resettable PTC, 1.1A Ih, 2.2A It  [FUSE-1206]
J4  CON50A
L25  TCE1210U  [EMI1012-ESD]
L27  TCE1210U  [EMI1012-ESD]
L28  TCE1210U  [EMI1012-ESD]
L30  TCE1210U  [EMI1012-ESD]
P22  HDMI-A  [SMT(HDMI-A)]
Q24  Dual N,0.5A,20V  [SOT-563-6]
R10  10K/1%  [RC0402]
R11  10K/1%  [RC0402]
R12  10K/1%  [RC0402]
R13  10K/1%  [RC0402]
R152  20K  [RC0402]
R153  1M  [RC0402]
R264  27.4K  [RC0402]
R270  20K  [RC0402]
R329  10K/1%  [RC0402]
R331  10K/1%  [RC0402]
R364  0R  [RC0402]
R365  0R  [RC0402]
R366  0R  [RC0402]
R367  0R  [RC0402]
R368  0R  [RC0402]
R369  0R  [RC0402]
R884  1K/1%  [RC0402]
U9  TXS0102  [MO-187DA-8]
U38  IP4220CZ6  [SOT23-6L]
U44  TXS0102  [MO-187DA-8]
U45  TXS0102  [MO-187DA-8]
sheet 11. M.2 for WiFi, LEDs
C223  4.7uF,6.3V  [C0603-08]
C224  1uF  [RC0402]
C238  4.7uF,6.3V  [C0603-08]
C242  4.7uF,6.3V  [C0603-08]
C243  1uF  [RC0402]
DS4  LED-GREEN  [LED-1206]
DS5  LED-YELLOW  [LED-1206]
P23  M.2 Key E Connector, H=4.2mm  [NGFF67P4HEkeySM]
Q6  0.5A,20V,Vgs max 6V  [SOT-563-6]
R89  10K  [RC0402]
R90  200R  [RC0402]
R91  200R  [RC0402]
R92  10K  [RC0402]
R234  10k  [RC0402]
R242  0R  [RC0402]
R256  0R  [RC0402]
R257  0R  [RC0402]
R260  10k  [RC0402]
R274  10k  [RC0402]
R275  10k  [RC0402]
SP12  SMT_SPACER_M1.6x3  [MINIPCIE-4-Spacer]
U7  74AUP1G07  [SC70]

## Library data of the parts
PCB1 = ATP-FITPC3.rev1.0: CLABCONF0: =SBEV-UCMIMX8PLUS; P/N: 188C04560
ZZ1 = PARSER_VERSION_1_1.0: CLABCONF0: DNP
C2 = 100nF,_10V,_X7R,_10%,_0402: CLABCONF0: =SBEV-UCMIMX8PLUS; P/N: 151B10400S
C3 = 100nF,_10V,_X7R,_10%,_0402_10: CLABCONF0: =SBEV-UCMIMX8PLUS; P/N: 151B10400S
C4 = 100nF,_10V,_X7R,_10%,_0402_11: CLABCONF0: =SBEV-UCMIMX8PLUS; P/N: 151B10400S
C5 = 100nF,_10V,_X7R,_10%,_0402_12: CLABCONF0: =SBEV-UCMIMX8PLUS; P/N: 151B10400S
C6 = 100nF,_10V,_X7R,_10%,_0402_5: CLABCONF0: =SBEV-UCMIMX8PLUS; P/N: 151B10400S
C7 = 100nF,_10V,_X7R,_10%,_0402_2: CLABCONF0: =SBEV-UCMIMX8PLUS; P/N: 151B10400S
C8 = 100nF,_10V,_X7R,_10%,_0402_9: CLABCONF0: =SBEV-UCMIMX8PLUS; P/N: 151B10400S
C9 = 100nF,_10V,_X7R,_10%,_0402_4: CLABCONF0: =SBEV-UCMIMX8PLUS; P/N: 151B10400S
C10 = 100nF,_10V,_X7R,_10%,_0402_7: CLABCONF0: =SBEV-UCMIMX8PLUS; P/N: 151B10400S
C11 = 100nF,_10V,_X7R,_10%,_0402_1: CLABCONF0: =SBEV-UCMIMX8PLUS; P/N: 151B10400S
C12 = 100nF,_10V,_X7R,_10%,_0402_3: CLABCONF0: =SBEV-UCMIMX8PLUS; P/N: 151B10400S
C13 = 100nF,_10V,_X7R,_10%,_0402_6: CLABCONF0: =SBEV-UCMIMX8PLUS; P/N: 151B10400S
C21 = 100nF,_10V,_X7R,_10%,_0402_8: CLABCONF0: =SBEV-UCMIMX8PLUS; P/N: 151B10400S
C340 = 10uF_10V_20%_0402_3: CLABCONF0: =SBEV-UCMIMX8PLUS
C341 = 10uF_10V_20%_0402_4: CLABCONF0: =SBEV-UCMIMX8PLUS
C342 = 10uF_10V_20%_0402_1: CLABCONF0: =SBEV-UCMIMX8PLUS
C344 = 10uF_10V_20%_0402_2: CLABCONF0: =SBEV-UCMIMX8PLUS
C345 = 10uF_10V_20%_0402: CLABCONF0: =SBEV-UCMIMX8PLUS
C346 = 10uF_10V_20%_0402_5: CLABCONF0: =SBEV-UCMIMX8PLUS
E3 E4 = HDR_1x2_100MIL_TH_JUMPER: CLABCONF0: =SBEV-UCMIMX8PLUS
P1 P2 = Hirose_DF40C-100DP-0.4V: CLABCONF0: =SBEV-UCMIMX8PLUS; P/N: 182K10004S
R69 = 10K,1%,0402,1_16W: CLABCONF0: =SBEV-UCMIMX8PLUS; P/N: 161C10011S
R160 = 4_0.75K,1%,0402,1_16W_3: CLABCONF0: =SBEV-UCMIMX8PLUS
R173 = 4_0.75K,1%,0402,1_16W: CLABCONF0: =SBEV-UCMIMX8PLUS
R188 = 4_0.75K,1%,0402,1_16W_1: CLABCONF0: =SBEV-UCMIMX8PLUS
R189 = 4_0.75K,1%,0402,1_16W_2: CLABCONF0: =SBEV-UCMIMX8PLUS
SW2-SW4 = TACT_SW_6x6mm_SMT: CLABCONF0: =SBEV-UCMIMX8PLUS
C60 C69 = Cap.,10uF,6.3V,0603,X5R: CLABCONF0: =SBEV-UCMIMX8PLUS
C61 C168 = 100nF,_10V,_X7R,_10%,_0402_7: CLABCONF0: =SBEV-UCMIMX8PLUS
C66 C169 = 100nF,_10V,_X7R,_10%,_0402_6: CLABCONF0: =SBEV-UCMIMX8PLUS
C1 C140 C142 C149 C202 C244 = 1uF,X5R,6.3V,0402: CLABCONF0: =SBEV-UCMIMX8PLUS
C27 C78 C86 C141 = 100nF,_10V,_X7R,_10%,_0402_1: CLABCONF0: =SBEV-UCMIMX8PLUS
C70 C77 C143 = 100nF,_10V,_X7R,_10%,_0402: CLABCONF0: =SBEV-UCMIMX8PLUS
C144 C170 = 100nF,_10V,_X7R,_10%,_0402_4: CLABCONF0: =SBEV-UCMIMX8PLUS
C146 C171 = 100nF,_10V,_X7R,_10%,_0402_5: CLABCONF0: =SBEV-UCMIMX8PLUS
C51 C84 C148 = 100nF,_10V,_X7R,_10%,_0402_3: CLABCONF0: =SBEV-UCMIMX8PLUS
C55 C76 C200 = 100nF,_10V,_X7R,_10%,_0402_2: CLABCONF0: =SBEV-UCMIMX8PLUS
P3 = Conn_1.,_Micro-USB,_B-Type: CLABCONF0: =SBEV-UCMIMX8PLUS; P/N: 180K00501S
P4 = microSD_push-pull: CLABCONF0: =SBEV-UCMIMX8PLUS; P/N: 182K01300S
P5 P6 = Con_0.,1GBit_RJ45,_short: CLABCONF0: =SBEV-UCMIMX8PLUS
R9 R10 R89 R217 R229 = 10K,1%,0402,1_16W_0: CLABCONF0: =SBEV-UCMIMX8PLUS
R46 R133 = 475R_1%,_0402: CLABCONF0: =SBEV-UCMIMX8PLUS
R47 R101 = 475R_1%,_0402_1: CLABCONF0: =SBEV-UCMIMX8PLUS
R76 R331 = 10K,1%,0402,1_16W_1: CLABCONF0: =SBEV-UCMIMX8PLUS
R134 R329 = 10K,1%,0402,1_16W: CLABCONF0: =SBEV-UCMIMX8PLUS
U24 = CP2104_1: CLABCONF0: =SBEV-UCMIMX8PLUS; P/N: 116A00140S
U9 U25 U44 U45 = TXS0102_0: CLABCONF0: =SBEV-UCMIMX8PLUS; P/N: 116A01020S
U26-U28 U33 U38 = IP4220CZ6_0: CLABCONF0: =SBEV-UCMIMX8PLUS
C81 C83 = 27pF,_50V,_X7R,_10%,_0402: CLABCONF0: =SBEV-UCMIMX8PLUS; P/N: 151D18000S
C87 = 27pF,_50V,_X7R,_10%,_0402: CLABCONF0: =SBEV-UCMIMX8PLUS; P/N: 151D10000S
C138 = 15pF,_50V,_NPO,_5%,_0402_8: CLABCONF0: =SBEV-UCMIMX8PLUS; P/N: 151B47500S
C139 = 15pF,_50V,_NPO,_5%,_0402_4: CLABCONF0: =SBEV-UCMIMX8PLUS; P/N: 151B47500S
C248 = 15pF,_50V,_NPO,_5%,_0402: CLABCONF0: =SBEV-UCMIMX8PLUS; P/N: 151B47500S
C249 = 15pF,_50V,_NPO,_5%,_0402_2: CLABCONF0: =SBEV-UCMIMX8PLUS; P/N: 151B10400S
C267 = 15pF,_50V,_NPO,_5%,_0402_12: CLABCONF0: =SBEV-UCMIMX8PLUS; P/N: 151B47500S
C268 = 15pF,_50V,_NPO,_5%,_0402_11: CLABCONF0: =SBEV-UCMIMX8PLUS; P/N: 151B10400S
C269 = 15pF,_50V,_NPO,_5%,_0402_7: CLABCONF0: =SBEV-UCMIMX8PLUS; P/N: 151B10400S
C270 = 15pF,_50V,_NPO,_5%,_0402_6: CLABCONF0: =SBEV-UCMIMX8PLUS; P/N: 151B10400S
C271 = 15pF,_50V,_NPO,_5%,_0402_5: CLABCONF0: =SBEV-UCMIMX8PLUS; P/N: 151B47500S
C272 = 15pF,_50V,_NPO,_5%,_0402_13: CLABCONF0: =SBEV-UCMIMX8PLUS; P/N: 151B10400S
C273 = 15pF,_50V,_NPO,_5%,_0402_3: CLABCONF0: =SBEV-UCMIMX8PLUS; P/N: 151B47500S
C274 = 15pF,_50V,_NPO,_5%,_0402_10: CLABCONF0: =SBEV-UCMIMX8PLUS; P/N: 151B10400S
C275 = 15pF,_50V,_NPO,_5%,_0402_1: CLABCONF0: =SBEV-UCMIMX8PLUS; P/N: 151B47500S
C276 = 15pF,_50V,_NPO,_5%,_0402_9: CLABCONF0: =SBEV-UCMIMX8PLUS; P/N: 151B10400S
FB4 = Ferrite_bead_,_120_Ohm@3A: CLABCONF0: =SBEV-UCMIMX8PLUS; P/N: 147D22101S
R99 R257 = 0R,_0402_0_1: CLABCONF0: =SBEV-UCMIMX8PLUS
R106 = 1.5K_1%,_0402: CLABCONF0: =SBEV-UCMIMX8PLUS
R122 R242 = 0R,_0402_0: CLABCONF0: =SBEV-UCMIMX8PLUS
R124 = 1M_,5%,_0402_1: CLABCONF0: =SBEV-UCMIMX8PLUS; P/N: 161C24911S
R128 = 4.75K,1%,0402,1_16W_7: CLABCONF0: DNP
R138 = 4.75K,1%,0402,1_16W_4: CLABCONF0: DNP
R162 = 0R,_0402_2: CLABCONF0: =SBEV-UCMIMX8PLUS
R163 R256 = 0R,_0402_0_2: CLABCONF0: =SBEV-UCMIMX8PLUS
R164 = 1M_,5%,_0402_2: CLABCONF0: =SBEV-UCMIMX8PLUS; P/N: 161C47511S
R168 R169 R234 = 1M_,5%,_0402: CLABCONF0: =SBEV-UCMIMX8PLUS; P/N: 161C10021S
R170 = 4.75K,1%,0402,1_16W_1: CLABCONF0: DNP
R177 = 0R,_0402_1: CLABCONF0: =SBEV-UCMIMX8PLUS
R41 R178 = 0R,_0402: CLABCONF0: =SBEV-UCMIMX8PLUS
R232 = 4.75K,1%,0402,1_16W: CLABCONF0: =SBEV-UCMIMX8PLUS
R233 = 4.75K,1%,0402,1_16W_2: CLABCONF0: =SBEV-UCMIMX8PLUS
R238 = 4.75K,1%,0402,1_16W_15: CLABCONF0: =SBEV-UCMIMX8PLUS
R251 = 4.75K,1%,0402,1_16W_12: CLABCONF0: DNP
R258 = 4.75K,1%,0402,1_16W_13: CLABCONF0: =SBEV-UCMIMX8PLUS
R262 = 4.75K,1%,0402,1_16W_8: CLABCONF0: DNP
R263 = 4.75K,1%,0402,1_16W_14: CLABCONF0: =SBEV-UCMIMX8PLUS
R265 = 4.75K,1%,0402,1_16W_10: CLABCONF0: =SBEV-UCMIMX8PLUS
R267 = 4.75K,1%,0402,1_16W_9: CLABCONF0: DNP
R269 = 4.75K,1%,0402,1_16W_11: CLABCONF0: DNP
R271 = 4.75K,1%,0402,1_16W_6: CLABCONF0: =SBEV-UCMIMX8PLUS
R272 = 4.75K,1%,0402,1_16W_3: CLABCONF0: =SBEV-UCMIMX8PLUS
R273 = 4.75K,1%,0402,1_16W_5: CLABCONF0: =SBEV-UCMIMX8PLUS
U14 = RTL8211FDI-40P_A_0: IC XCVR ETH INTEGRATED 10/100/1000MBPS RGMII 3.3V/2.5V/1.8V QFN40; 3D_Mechanical_Footprint_File: http://fcl.am.freescale.net/ALLEGRO/step/qfn40_0p4_5x5mm.STEP; AGILE_PN: TMP-CIP-10596; CAD_APPROVED: Yes; CLABCONF0: =SBEV-UCMIMX8PLUS; HEIGHT: 0.9MM; MFG_NAME01: REALTEK SEMICONDUCTOR; P/N: 116A00640S; PRE_APN: 312-83499; Package Size: QFN40; ROHS: Yes; Temp Range: -40  °C  +85 °C
X1 = XTAL,_25.000Mhz,_3x5mm: CLABCONF0: =SBEV-UCMIMX8PLUS; P/N: 141B25603I
C127 = 100nF,_10V,_X7R,_10%,_0402_1: CLABCONF0: =SBEV-UCMIMX8PLUS; Group: LAN2
C153 = 100nF,_10V,_X7R,_10%,_0402_3: CLABCONF0: =SBEV-UCMIMX8PLUS; Group: LAN2
C176 = 100nF,_10V,_X7R,_10%,_0402_2: CLABCONF0: =SBEV-UCMIMX8PLUS; P/N: 151C10500S
C182 = 100nF,_10V,_X7R,_10%,_0402_4: CLABCONF0: =SBEV-UCMIMX8PLUS; P/N: 151C10500S
C194 C201 C225 = 10uF,6_0.3V,0603,20%X5R: CLABCONF0: =SBEV-UCMIMX8PLUS
C195 = 100nF,_10V,_X7R,_10%,_0402: CLABCONF0: =SBEV-UCMIMX8PLUS; Group: LAN2
C230 = 10uF,6.3V,0603,20%,X5R_0: CLABCONF0: =SBEV-UCMIMX8PLUS
J3 = USB3_TYPEA_CONNECTER_0: CLABCONF0: =SBEV-UCMIMX8PLUS
L1 L2 L7 L11-L16 L25 L27 L28 L30 L59-L63 = ESD_CHOKE_DIFFx2_10: CLABCONF0: =SBEV-UCMIMX8PLUS; P/N: 142D11801S
P21 = Conn.,_Micro-USB,_B-Type: CLABCONF0: =SBEV-UCMIMX8PLUS; P/N: 180K00501S
R30 = RESISTOR: CLABCONF0: =SBEV-UCMIMX8PLUS; P/N: 161C14721S
R11 R52 R92 R172 = 10K,1%,0402,1_16W_0_1: CLABCONF0: =SBEV-UCMIMX8PLUS
R176 R274 = 1M_,5%,_0402_1: CLABCONF0: =SBEV-UCMIMX8PLUS; P/N: 161C10021S
R191 R193 = 100K,_0402_0: CLABCONF0: =SBEV-UCMIMX8PLUS
R194 R260 = 1M_,5%,_0402_2: CLABCONF0: =SBEV-UCMIMX8PLUS; P/N: 161C10021S
R201 R275 = 1M_,5%,_0402_3: CLABCONF0: =SBEV-UCMIMX8PLUS; P/N: 161C10021S
U34 U42 = USB2_0.0_mux: CLABCONF0: =SBEV-UCMIMX8PLUS; P/N: 116A72220S
U41 = RT9703,3A_Power_switch+FLG: CLABCONF0: =SBEV-UCMIMX8PLUS; P/N: 124S10080S
U46 = 7SZ32_OR_sgl_SC70: CLABCONF0: =SBEV-UCMIMX8PLUS
C52 = 10uF,6.3V,0603,20%X5R_1: CLABCONF0: =SBEV-UCMIMX8PLUS
C56 = 10uF,6.3V,0603,20%X5R_2: CLABCONF0: =SBEV-UCMIMX8PLUS
C57 C278 = 1uF,X5R,6.3V,0402: CLABCONF0: =SBEV-UCMIMX8PLUS; P/N: 151D10510S
C58 = 100nF,_10V,_X7R,_10%,_0402: CLABCONF0: =SBEV-UCMIMX8PLUS; P/N: 151C22400S
C85 = 10uF,6.3V,0603,20%X5R: CLABCONF0: =SBEV-UCMIMX8PLUS
C245 = 10uF,6_0.3V,0603,20%X5R: CLABCONF0: =SBEV-UCMIMX8PLUS; P/N: 151C10611S
D2 D11 = BAT54WS_0: CLABCONF0: =SBEV-UCMIMX8PLUS
D7 = ZENER_24V_500mW_SOD-123: CLABCONF0: DNP
L8 = INC_DELTA_SI43-100,_10uH_1: CLABCONF0: =SBEV-UCMIMX8PLUS; CLABCONF1: <null>
L9 = INC_DELTA_SI43-100,_10uH: CLABCONF0: =SBEV-UCMIMX8PLUS; CLABCONF1: <null>
P12 P14 = HDR_2x12_100MIL_0: CLABCONF0: =SBEV-UCMIMX8PLUS; P/N: 190C02000S
P13 = HDR_2x5_100MIL_SMT_2: CLABCONF0: =SBEV-UCMIMX8PLUS; P/N: 190C00801S
R39 = 2.2R,5%,0402,1_16W_3: CLABCONF0: =SBEV-UCMIMX8PLUS; P/N: 161C06R25S
R63 = 2.2R,5%,0402,1_16W_2: CLABCONF0: =SBEV-UCMIMX8PLUS; P/N: 161C00005S
R65 = 2.2R,5%,0402,1_16W_1: CLABCONF0: =SBEV-UCMIMX8PLUS; P/N: 161C0R751S
R66 = 2.2R,5%,0402,1_16W: CLABCONF0: DNP; P/N: 161C06R25S
R81 = 2.2K,5%,0402.1_16W: CLABCONF0: =SBEV-UCMIMX8PLUS
R82 = 2.2K,5%,0402.1_16W_2: CLABCONF0: =SBEV-UCMIMX8PLUS
R83 = 2.2K,5%,0402.1_16W_1: CLABCONF0: =SBEV-UCMIMX8PLUS
U5 = TPS61165DBVT: CLABCONF0: =SBEV-UCMIMX8PLUS; P/N: 123C15100S
U15 = AIC1647_0: CLABCONF0: =SBEV-UCMIMX8PLUS; P/N: 123C40000S
C65 = 100nF,_10V,_X7R,_10%,_0402_9: CLABCONF0: =SBEV-UCMIMX8PLUS
C67 = 100nF,_10V,_X7R,_10%,_0402_8: CLABCONF0: =SBEV-UCMIMX8PLUS
C82 = 10nF,_25V,_X7R,_10%,_0402: CLABCONF0: =SBEV-UCMIMX8PLUS
C359 = Cap_1uF,X5R,6.3V,0402: CLABCONF0: =SBEV-UCMIMX8PLUS
D23-D25 = 1A_Schottky_Barrier_Rectifier: CLABCONF0: =SBEV-UCMIMX8PLUS
F4 = Fuse,_0.75A_Ih,_1.5A_It: CLABCONF0: =SBEV-UCMIMX8PLUS; P/N: 175P22200S
J4 = CON50A: CLABCONF0: =SBEV-UCMIMX8PLUS; P/N: 182K05001S
P22 = HDMI_Connector: CLABCONF0: =SBEV-UCMIMX8PLUS
Q6 Q24 = DUAL_N-MOSFET,_0.5A_20V: CLABCONF0: =SBEV-UCMIMX8PLUS
R12 = 10K,1%,0402,1_16W_0_2: CLABCONF0: =SBEV-UCMIMX8PLUS
R13 = 10K,1%,0402,1_16W_0_3: CLABCONF0: =SBEV-UCMIMX8PLUS
R152 R270 = RESISTOR: CLABCONF0: =SBEV-UCMIMX8PLUS; P/N: 161C20021S
R153 = RESISTOR: CLABCONF0: =SBEV-UCMIMX8PLUS; P/N: 161C10045S
R264 = RESISTOR: CLABCONF0: =SBEV-UCMIMX8PLUS; P/N: 161C27421S
R364 = 0R,_0402_0_2: CLABCONF0: =SBEV-UCMIMX8PLUS; P/N: 161C00005S
R365 = 0R,_0402_0_5: CLABCONF0: =SBEV-UCMIMX8PLUS; P/N: 161C00005S
R366 = 0R,_0402_0: CLABCONF0: DNP; P/N: 161C00005S
R367 = 0R,_0402_0_3: CLABCONF0: DNP; P/N: 161C00005S
R368 = 0R,_0402_0_1: CLABCONF0: =SBEV-UCMIMX8PLUS; P/N: 161C00005S
R369 = 0R,_0402_0_4: CLABCONF0: =SBEV-UCMIMX8PLUS; P/N: 161C00005S
R884 = 1K,1%,0402,1_16W: CLABCONF0: =SBEV-UCMIMX8PLUS
C223 = 100nF,_10V,_X7R,_10%,_0402: CLABCONF0: =SBEV-UCMIMX8PLUS; P/N: 151B10610S
C224 = 15pF,_50V,_NPO,_5%,_0402: CLABCONF0: =SBEV-UCMIMX8PLUS; P/N: 151B10500S
C238 = 100nF,_10V,_X7R,_10%,_0402_1: CLABCONF0: =SBEV-UCMIMX8PLUS; P/N: 151B10610S
C242 = 100nF,_10V,_X7R,_10%,_0402_2: CLABCONF0: =SBEV-UCMIMX8PLUS; P/N: 151B10610S
C243 = 15pF,_50V,_NPO,_5%,_0402_1: CLABCONF0: =SBEV-UCMIMX8PLUS; P/N: 151B10500S
DS4 = LED-GREEN_1206_2: CLABCONF0: =SBEV-UCMIMX8PLUS
DS5 = LED-RED_1206: CLABCONF0: =SBEV-UCMIMX8PLUS; P/N: 139A10110S
P23 = M.2_Key_E_Connector: CLABCONF0: =SBEV-UCMIMX8PLUS; P/N: 182K06701S
R90 = 348R,1%,0402,1_16W: CLABCONF0: =SBEV-UCMIMX8PLUS; P/N: 161C20001S
R91 = 348R,1%,0402,1_16W_1: CLABCONF0: =SBEV-UCMIMX8PLUS; P/N: 161C20001S
SP12 = SMT_SPACER_M2x3_1: CLABCONF0: =SBEV-UCMIMX8PLUS; P/N: 383B54510S
U7 = 74AUP1G07_,_buffer_,LV: CLABCONF0: =SBEV-UCMIMX8PLUS

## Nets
5V0_USB: C176.2 C201.1 C225.2 J3.1(VBUS) R201.2 U41.2(Vout) U41.3(Vout) ; also on sheet 10
GND: C1.2 C2.2 C3.2 C4.2 C5.2 C6.2 C7.2 C8.2 C9.2 C10.2 C11.2 C12.2 C13.2 C21.2 C27.2 C51.2 C52.2 C55.2 C56.2 C57.2 C58.2 C60.2 C61.2 C65.1 C66.2 C67.1 C69.2 C70.2 C76.2 C77.2 C78.2 C81.1 C82.1 C83.1 C84.2 C86.2 C87.2 C127.1 C138.1 C139.1 C140.2 C141.2 C142.2 C143.2 C144.2 C146.2 C148.2 C149.2 C153.1 C168.2 C169.2 C170.2 C171.2 C176.1 C182.1 C194.2 C195.1 C200.2 C201.2 C202.1 C223.1 C224.1 C225.1 C230.1 C238.1 C242.1 C243.1 C244.1 C248.1 C249.1 C267.1 C268.1 C269.1 C270.1 C271.1 C272.1 C273.1 C274.1 C275.1 C276.1 C278.2 C340.2 C341.2 C342.2 C344.2 C345.2 C346.2 C359.2 E4.2 J3.4(GND) J3.7(GND) J3.SH1 J3.SH2 J4.1 J4.2 J4.7 J4.8 J4.14 J4.25 J4.26 J4.31 J4.32 J4.37 J4.38 J4.44 L1.5(GND) L1.6(GND) L2.5(GND) L2.6(GND) L7.5(GND) L7.6(GND) L11.5(GND) L11.6(GND) L12.5(GND) L12.6(GND) L13.5(GND) L13.6(GND) L14.5(GND) L14.6(GND) L15.5(GND) L15.6(GND) L16.5(GND) L16.6(GND) L25.5(GND) L25.6(GND) L27.5(GND) L27.6(GND) L28.5(GND) L28.6(GND) L30.5(GND) L30.6(GND) L59.5(GND) L59.6(GND) L60.5(GND) L60.6(GND) L61.5(GND) L61.6(GND) L62.5(GND) L62.6(GND) L63.5(GND) L63.6(GND) P1.4 P1.10 P1.20 P1.40 P1.54 P1.64 P1.78 P1.88 P2.10 P2.16 P2.22 P2.28 P2.34 P2.40 P2.46 P2.54 P2.72 P2.82 P3.5(GND) P3.6(SHIELD1) P3.7(SHIELD2) P3.8(SHIELD3) P3.9(SHIELD4) P4.G1 P4.G2 P4.G3 P4.G4 P4.P6(VSS) P4.SH1 P4.SH2 P5.S1(SHIELD) P5.S2(SHIELD) P6.S1(SHIELD) P6.S2(SHIELD) P12.1 P12.2 P12.7 P12.8 P12.13 P12.14 P13.8 P14.1 P14.2 P14.7 P14.8 P14.13 P14.14 P21.5(GND) P21.6(SHIELD1) P21.7(SHIELD2) P21.8(SHIELD3) P21.9(SHIELD4) P22.2(D2_Shield) P22.5(D1_Shield) P22.8(D0_Shield) P22.11(CK_Shield) P22.17(GND) P22.20(SHELL1) P22.21(SHELL2) P23.1(GND) P23.7(GND) P23.13(SDIO_D0) P23.18(GND) P23.19(SDIO_D3) P23.33(GND) P23.39(GND) P23.45(GND) P23.51(GND) P23.57(GND) P23.63(GND) P23.69(GND) P23.75(GND) Q6.1(S1) Q6.4(S2) R30.2 R39.2 R46.2 R47.2 R63.2 R81.2 R82.2 R83.2 R89.1 R92.1 R124.1 R138.2 R172.1 R193.2 R217.1 R232.2 R238.2 R262.2 R263.2 R265.2 R267.2 R269.2 R272.2 R884.2 SP12.NC(1) SW3.1 SW3.3 SW4.1 SW4.3 U5.4(GND) U7.3(GND) U9.2(GND) U14.41(GND) U15.2(GND) U24.2(GND) U24.25(CPAD) U25.2(GND) U26.2(GND) U27.2(GND) U28.2(GND) U33.2(GND) U34.4(GND) U38.2(GND) U41.4(GND) U42.4(GND) U44.2(GND) U45.2(GND) U46.3(GND) X1.2 X1.4 ; also on sheet 9 10 11 12 13
VCC_1V8: C77.1 C86.1 C169.1 C171.1 J4.13 J4.49 R160.1 R162.2 R173.1 R188.1 R189.1 R275.2 R329.2 R331.2 U7.5(VCC) U44.3(VCCA) U45.3(VCCA) ; also on sheet 9 11 12
VCC_3V3: C1.1 C27.1 C51.1 C52.1 C65.2 C76.1 C84.1 C127.2 C143.1 C146.1 C148.1 C149.1 C153.2 C168.1 C170.1 C200.1 C202.2 C223.2 C224.2 C238.2 C242.2 C243.2 C244.2 C271.2 C272.2 D24.2(ANODE) DS4.ANODE DS5.ANODE FB4.2 J4.20 J4.50 L8.1 P4.P4(VDD) P6.P12(LED1_A) P6.P14(LED2_A) P12.20 P13.2 P14.20 P23.2(+3.3V) P23.4(+3.3V) P23.50(SUSCLK) P23.72(+3.3V) P23.74(+3.3V) Q24.2(G1) Q24.5(G2) R9.1 R12.1 R13.1 R69.1 R76.2 R152.2 R153.2 R164.1 R168.2 R176.2 R229.1 R234.2 R260.2 R270.1 R271.1 R273.1 R274.2 U9.3(VCCA) U14.29(DVDD33) U15.6(IN) U25.3(VCCA) U27.5(VBUS) U28.5(VBUS) U33.5(VBUS) U34.9(VCC) U42.9(VCC) U44.7(VCCB) U45.7(VCCB) ; also on sheet 9 10 11 12 13
VCC_5V0: C55.1 C56.1 C195.2 C230.2 F4.2 L9.1 R52.1 R191.1 U5.1(IN) U41.6(Vin) U41.7(Vin) U46.5(VCC) ; also on sheet 9 11 12 13
VCC_RTC: P1.93 ; also on sheet 11
ALT_BOOT: E3.1 P1.90 SW2.2 SW2.4
CAN2_RX/SAI2_MCLK: P1.49 ; also on sheet 13
CAN2_TX/SAI2_TXD0: P1.33 ; also on sheet 13
CON_UART_RXD: U24.21(TXD) U25.8(B1)
CON_UART_TXD: U24.20(RXD) U25.1(B2)
CSI1_CTRL: J4.19 ; also on sheet 13
CSI1_FLASH_OUT: J4.23 ; also on sheet 13
CSI1_PWR_DWN: J4.22 ; also on sheet 13
CSI1_RST: J4.24 ; also on sheet 13
CSI1_TRG: J4.21 ; also on sheet 13
CSI2_CTRL: J4.43 ; also on sheet 13
CSI2_FLASH_OUT: J4.47 ; also on sheet 13
CSI2_PWR_DWN: J4.46 ; also on sheet 13
CSI2_RST: J4.48 ; also on sheet 13
CSI2_TRG: J4.45 ; also on sheet 13
DSI1_CN: L61.2 P12.5
DSI1_CP: L61.1 P12.3
DSI1_N0: L59.2 P12.6
DSI1_N1: L60.2 P12.11
DSI1_N2: L62.2 P12.12
DSI1_N3: L63.2 P12.18
DSI1_P0: L59.1 P12.4
DSI1_P1: L60.1 P12.9
DSI1_P2: L62.1 P12.10
DSI1_P3: L63.1 P12.16
DSI_BCKLIGHT_FB: D7.2(ANODE) R41.2 U15.3(FB)
DSI_DISP_RESET: P12.17 R81.1 ; also on sheet 13
DSI_LED_A: C245.2 C278.1 D2.CATHODE D7.1(CATHODE) P12.19 U15.5(OVP)
DSI_LED_K: C245.1 P12.15 R39.1 R41.1
DSI_WLD_SW: D2.ANODE L8.2 U15.1(LX)
ECSPI2_MISO: P2.89 ; also on sheet 13
ECSPI2_MOSI: P2.95 ; also on sheet 13
ECSPI2_SCLK: P2.93 ; also on sheet 13
ECSPI2_SS0: P2.91 ; also on sheet 13
ENET1_INT/SAI2_RXFS: P2.88 R122.2
ENET1_MDC/SD1_CLK: P2.68 U14.13(MDC)
ENET1_MDIO/SD1_CMD: P2.70 R106.1 U14.14(MDIO)
ENET1_nRST: R99.1 R168.1 U14.12(~{PHYRST})
ENET1_nRST/SAI2_TXFS: P2.76 R99.2
ENET1_RD0/SD1_DATA2: P2.41 R138.1 R258.2 U14.25(RXD0/RXDLY)
ENET1_RD1/SD1_DATA3: P2.43 R170.1 R232.1 U14.24(RXD1/TXDLY)
ENET1_RD2/SAI1_RXD6: P2.45 R128.2 R265.1 U14.23(RXD2/PLLOFF)
ENET1_RD3/SAI1_RXD7: P2.47 R251.1 R263.1 U14.22(RXD3/PHYAD0)
ENET1_RX_CTL/SAI1_TXFS: P2.53 R233.1 R262.1 U14.26(RXCTL/PHYAD2)
ENET1_RXC/SAI1_TXC: P2.55 R163.2 R238.1
ENET1_TD0/SD1_DATA1: P2.59 U14.18(TXD0)
ENET1_TD1/SD1_DATA0: P2.61 U14.17(TXD1)
ENET1_TD2/SAI1_TXD2: P2.63 U14.16(TXD2)
ENET1_TD3/SAI1_TXD3: P2.65 U14.15(TXD3)
ENET1_TX_CTL/SAI1_TXD4: P2.67 U14.19(TXCTL)
ENET1_TXC/SAI1_TXD5: C87.1 P2.69 U14.20(TXC)
ETH0_CT1: C60.1 C61.1 P5.P5(CT)
ETH0_CT2: C66.1 P5.P6(CT)
ETH0_GREEN_LED_CAT: P5.P11(LED1_C) R46.1
ETH0_LED_ACT/PHY1ADDRESS2: P2.83 P5.P12(LED1_A)
ETH0_LINK-LED_10_100: P2.86 P5.P14(LED2_A)
ETH0_MDI0N: P2.73 P5.P2(MDI0-)
ETH0_MDI0P: P2.74 P5.P1(MDI0+)
ETH0_MDI1N: P2.80 P5.P4(MDI1-)
ETH0_MDI1P: P2.78 P5.P3(MDI1+)
ETH0_MDI2N: P2.81 P5.P8(MDI2-)
ETH0_MDI2P: P2.79 P5.P7(MDI2+)
ETH0_MDI3N: P2.85 P5.P10(MDI3-)
ETH0_MDI3P: P2.84 P5.P9(MDI3+)
ETH0_YELLOW_LED_CAT: P5.P13(LED2_C) R47.1
ETH1_1V0: C248.2 C249.2 R177.1 R178.1 U14.30(LDO_OUT)
ETH1_AVDD10: C138.2 C139.2 C269.2 C270.2 R177.2 U14.3(AVDD10_1) U14.8(AVDD10_2) U14.38(AVDD10_3)
ETH1_AVDD33: C273.2 C274.2 FB4.1 U14.11(AVDD33_1) U14.40(AVDD33_2)
ETH1_CT1A: C69.1 C70.1 P6.P5(CT)
ETH1_CT2A: C78.1 P6.P6(CT)
ETH1_DVDD10: C267.2 C268.2 R178.2 U14.21(DVDD10)
ETH1_DVDD_RG: C275.2 C276.2 R106.2 R128.1 R162.1 R170.2 R233.2 R251.2 R258.1 U14.28(DVDD_RG)
ETH1_LED0/CFG_EXT: R101.2 R267.1 R271.2 U14.32(LED0/CFG_EXT)
ETH1_LED1/CFG_LDO0: R272.1 U14.33(LED1/CFG_LDO0)
ETH1_LED2/CFG_LDO1: R133.2 R269.1 R273.2 U14.34(LED2/CFG_LDO1)
ETH1_MDI0N: P6.P2(MDI0-) U14.2(MDIN0)
ETH1_MDI0P: P6.P1(MDI0+) U14.1(MDIP0)
ETH1_MDI1N: P6.P4(MDI1-) U14.5(MDIN1)
ETH1_MDI1P: P6.P3(MDI1+) U14.4(MDIP1)
ETH1_MDI2N: P6.P8(MDI2-) U14.7(MDIN2)
ETH1_MDI2P: P6.P7(MDI2+) U14.6(MDIP2)
ETH1_MDI3N: P6.P10(MDI3-) U14.10(MDIN3)
ETH1_MDI3P: P6.P9(MDI3+) U14.9(MDIP3)
ETH1_RSET: R124.2 U14.39(RSET)
GBEPHY1_CLK_XIN: C81.2 U14.36(XTAL_IN) X1.3
GBEPHY1_CLK_XOUT: C83.2 U14.37(XTAL_OUT/_EXT_CLK) X1.1
GPIO1_00: P1.59 ; also on sheet 13
GPIO1_01/PWM1_OUT: P1.98 ; also on sheet 13
HDMI_5V_FL: C359.1 D23.2(ANODE) F4.1
HDMI_5VSCHT: C67.2 C82.2 D23.1(CATHODE) P22.18(+5V) R10.1 R11.1 R884.1 U9.7(VCCB) U38.5(VBUS)
HDMI_CEC: D25.2(ANODE) P1.85 Q24.4(S2) R152.1
HDMI_CEC_3P3: D25.1(CATHODE) P22.13(CE_Remote) Q24.3(D2) R264.1 U38.6(IO4)
HDMI_DDC_SCL: P1.70 R12.2 U9.5(A1)
HDMI_DDC_SDA: P1.63 R13.2 U9.4(A2)
HDMI_HPD: P1.92 Q24.1(S1) R153.1
HDMI_HPD_5V: P22.19(HP_DET) Q24.6(D1) U38.1(IO1)
HDMI_TX0N: L28.3 P1.31
HDMI_TX0P: L28.4 P1.29
HDMI_TX1N: L25.3 P1.41
HDMI_TX1P: L25.4 P1.39
HDMI_TX2N: L27.3 P1.47
HDMI_TX2P: L27.4 P1.45
HDMI_TXCN: L30.3 P1.25
HDMI_TXCP: L30.4 P1.23
HOST1_USB_DN: J3.2(DN) L11.4
HOST1_USB_DP: J3.3(DP) L11.3
I2C3_SCL: P1.94 P13.1 U33.1(IO1) ; also on sheet 9 13
I2C3_SDA: P1.91 P13.3 U33.3(IO2) ; also on sheet 9 13
I2C4_SCL/GPIO5_IO20/PWM2_OUT: P2.90 ; also on sheet 13
I2C5_SCL/SAI5_RXD0: P1.100 R188.2 U44.4(A2)
I2C5_SCL_3V3: R364.2 R366.2 U44.1(B2) ; also on sheet 13
I2C5_SDA/SAI5_MCLK: P1.96 R160.2 U44.5(A1)
I2C5_SDA_3V3: R365.2 R367.2 U44.8(B1) ; also on sheet 13
I2C6_SCL/SAI5_RXFS: P1.87 R189.2 U45.4(A2)
I2C6_SCL_3V3: R368.2 U45.1(B2)
I2C6_SDA/SAI5_RXC: P1.89 R173.2 U45.5(A1)
I2C6_SDA_3V3: R369.2 U45.8(B1)
JTAG_MOD: P1.75 ; also on sheet 13
JTAG_TCK: P1.73 ; also on sheet 13
JTAG_TDI: P1.71 ; also on sheet 13
JTAG_TDO: P1.67 ; also on sheet 13
JTAG_TMS: P1.65 ; also on sheet 13
LVDS0_CLK_N: L13.3 P1.82
LVDS0_CLK_P: L13.4 P1.80
LVDS0_CLKN: L13.2 P14.5
LVDS0_CLKP: L13.1 P14.3
LVDS0_D0_N: L2.4 P1.44
LVDS0_D0_P: L2.3 P1.42
LVDS0_D1_N: L1.4 P1.48
LVDS0_D1_P: L1.3 P1.46
LVDS0_D2_N: L7.4 P1.52
LVDS0_D2_P: L7.3 P1.50
LVDS0_D3_N: L12.4 P1.58
LVDS0_D3_P: L12.3 P1.56
LVDS0_N0: L2.1 P14.6
LVDS0_N1: L1.1 P14.11
LVDS0_N2: L7.1 P14.12
LVDS0_N3: L12.1 P14.18
LVDS0_P0: L2.2 P14.4
LVDS0_P1: L1.2 P14.9
LVDS0_P2: L7.2 P14.10
LVDS0_P3: L12.2 P14.16
LVDS_COMP: C58.1 U5.5(COMP)
LVDS_DISP_RESET: P14.17 R83.1 ; also on sheet 13
LVDS_LED_NEG: C85.1 P14.15 R65.1 R66.1 U5.6(FB)
LVDS_LED_POS: C57.1 C85.2 D11.CATHODE P14.19
LVDS_RESET: R63.1 R65.2 R66.2
LVDS_WLD_SW: D11.ANODE L9.2 U5.3(SW)
M2_PCIE_CLKN: P23.49(REFCLKN) R256.2
M2_PCIE_CLKP: P23.47(REFCLKP) R242.2
M2_PCIE_CLKREQ#: P23.53(CLKREQ#) R257.2
MIPI_CSI1_CLK_N: J4.5 P2.2
MIPI_CSI1_CLK_P: J4.3 P2.4
MIPI_CSI1_D0_N: J4.6 P2.6
MIPI_CSI1_D0_P: J4.4 P2.8
MIPI_CSI1_D1_N: J4.11 P2.31
MIPI_CSI1_D1_P: J4.9 P2.33
MIPI_CSI1_D2_N: J4.12 P2.25
MIPI_CSI1_D2_P: J4.10 P2.27
MIPI_CSI1_D3_N: J4.18 P2.35
MIPI_CSI1_D3_P: J4.16 P2.37
MIPI_CSI1_I2C_SCL: J4.15 R364.1
MIPI_CSI1_I2C_SDA: J4.17 R365.1
MIPI_CSI2_CLK_N: J4.29 P2.12
MIPI_CSI2_CLK_P: J4.27 P2.14
MIPI_CSI2_D0_N: J4.30 P2.18
MIPI_CSI2_D0_P: J4.28 P2.20
MIPI_CSI2_D1_N: J4.35 P2.24
MIPI_CSI2_D1_P: J4.33 P2.26
MIPI_CSI2_D2_N: J4.36 P2.48
MIPI_CSI2_D2_P: J4.34 P2.50
MIPI_CSI2_D3_N: J4.42 P2.56
MIPI_CSI2_D3_P: J4.40 P2.58
MIPI_CSI2_I2C_SCL: J4.39 R366.1 R368.1
MIPI_CSI2_I2C_SDA: J4.41 R367.1 R369.1
MIPI_DSI1_CLK_N: L61.3 P2.21
MIPI_DSI1_CLK_P: L61.4 P2.23
MIPI_DSI1_D0_N: L59.3 P2.1
MIPI_DSI1_D0_P: L59.4 P2.3
MIPI_DSI1_D1_N: L60.3 P2.15
MIPI_DSI1_D1_P: L60.4 P2.17
MIPI_DSI1_D2_N: L62.3 P2.5
MIPI_DSI1_D2_P: L62.4 P2.7
MIPI_DSI1_D3_N: L63.3 P2.11
MIPI_DSI1_D3_P: L63.4 P2.13
MUX_HOST_USB1_DN: L11.1 U42.7(HSD1-)
MUX_HOST_USB1_DP: L11.2 U42.1(HSD1+)
MUX_M2_USB1_DN: P23.5(USB_D-) U42.6(HSD2-)
MUX_M2_USB1_DP: P23.3(USB_D+) U42.2(HSD2+)
MUX_USB1_DN: U34.7(HSD1-) U42.5(D-)
MUX_USB1_DP: U34.1(HSD1+) U42.3(D+)
MUX_USB_SDP_DN: L16.1 U34.6(HSD2-)
MUX_USB_SDP_DP: L16.2 U34.2(HSD2+)
OE_DDC_LS: R270.2 U9.6(OE)
PCIe_PWAKE: P23.55(WAKE#) R274.1
PCIE_REF_CLKN: P2.44 R256.1
PCIE_REF_CLKP: P2.42 R242.1
PCIE_RXN_N: P2.30 P23.43(PERN0)
PCIE_RXN_P: P2.32 P23.41(PERP0)
PCIE_TXN_N: P2.36 P23.37(PETN0)
PCIE_TXN_P: P2.38 P23.35(PETP0)
PHY1_INT: R122.1 R164.2 U14.31(~{INT}/~{PME})
PHY1_RXC: R163.1 U14.27(RXC/PHYAD1)
PMIC_ON_REQ: P1.68 ; also on sheet 12 13
PMIC_STBY_REQ: P1.66 ; also on sheet 12 13
PWM1_OUT/SPDIF_EXT_CLK: P1.77 R229.2 U15.4(EN/PWM)
PWRBTN: P2.64 SW4.2 SW4.4
SAI1_MCLK/GPIO4_IO20: P2.52 ; also on sheet 9
SAI1_TXD0/GPIO4_12: P2.60 Q6.2(G1) R89.2
SAI1_TXD7/GPIO4_IO19: P1.60 R275.1 U7.2(IN)
SAI2_RXC/GPIO4_IO22: P1.53 ; also on sheet 9
SAI2_TXC/GPIO4_IO25: P1.51 ; also on sheet 13
SAI3_MCLK: P1.30 ; also on sheet 9
SAI3_RXC/GPIO4_IO29: P1.32 ; also on sheet 10
SAI3_RXD/UART2_RTS: P1.28 ; also on sheet 9
SAI3_RXFS/GPIO4_IO28: P1.34 P13.5 U33.4(IO3)
SAI3_TXC: P1.36 ; also on sheet 9
SAI3_TXD: P1.26 ; also on sheet 9
SAI3_TXFS: P1.38 ; also on sheet 9
SD1_RESET_B/GPIO2_IO10: P2.62 ; also on sheet 9
SD2_CLK: P2.96 P4.P5(CLK) U27.3(IO2)
SD2_CMD: P2.100 P4.P3(CMD) U28.6(IO4)
SD2_DATA0: P2.97 P4.P7(DAT0) U27.1(IO1)
SD2_DATA1: P2.99 P4.P8(DAT1) U27.6(IO4)
SD2_DATA2: P2.94 P4.P1(DAT2) U28.1(IO1)
SD2_DATA3: P2.98 P4.P2(DAT3) U28.4(IO3)
SD2_nCD: P2.92 P4.P9(CD#) R9.2
SD2_WP/GPIO2_IO20: P2.49 Q6.5(G2) R92.2
SERIAL_VBUSIN: C142.1 P3.1(VBUS) U24.7(REGIN) U24.8(VBUS) U26.5(VBUS)
SPDIF_RX: P1.79 R52.2 U5.2(CTRL)
SPDIF_TX: P1.81 ; also on sheet 13
SYS_RST_PMIC: P1.2 SW3.2 SW3.4 ; also on sheet 13
TMDS1_CLK_LN: L30.2 P22.12(CK-)
TMDS1_CLK_LP: L30.1 P22.10(CK+)
TMDS1_DCLK: P22.15(DDC_CLK) R10.2 U9.8(B1) U38.4(IO3)
TMDS1_DDAT: P22.16(DDC_DATA) R11.2 U9.1(B2) U38.3(IO2)
TMDS1_TX0_LN: L28.2 P22.9(D0-)
TMDS1_TX0_LP: L28.1 P22.7(D0+)
TMDS1_TX1_LN: L25.2 P22.6(D1-)
TMDS1_TX1_LP: L25.1 P22.4(D1+)
TMDS1_TX2_LN: L27.2 P22.3(D2-)
TMDS1_TX2_LP: L27.1 P22.1(D2+)
TOUCH_RESET: P13.7 R82.1 U33.6(IO4) ; also on sheet 13
UART1_CTS/UART3_RXD: P1.21 ; also on sheet 13
UART1_RTS/UART3_TXD: P1.61 ; also on sheet 13
UART1_RXD: P1.19 ; also on sheet 13
UART1_TXD: P1.72 ; also on sheet 13
UART2_RXD: P1.76 U25.5(A1)
UART2_TXD: P1.74 U25.4(A2)
UART4_RXD: P1.84 ; also on sheet 13
UART4_TXD: P1.86 ; also on sheet 13
USB1_DN: P1.14 U34.5(D-)
USB1_DP: P1.12 U34.3(D+)
USB1_M2_SEL: E4.1 R176.1 U42.10(SEL)
USB1_RX_N: L15.2 P1.8
USB1_RX_P: L15.1 P1.6
USB1_SDP_SEL: R30.1 R169.1 U34.10(SEL)
USB1_SSRXN: J3.5(SSRXN) L15.3
USB1_SSRXP: J3.6(SSRXP) L15.4
USB1_SSTXN: J3.8(SSTXN) L14.3
USB1_SSTXP: J3.9(SSTXP) L14.4
USB1_TX_N: L14.2 P1.18
USB1_TX_P: L14.1 P1.16
USB1_VBUS: P1.24 U46.4(A+B)
USB2_DN: P1.5 ; also on sheet 10
USB2_DP: P1.3 ; also on sheet 10
USB2_RX_N: P1.9 ; also on sheet 10
USB2_RX_P: P1.7 ; also on sheet 10
USB2_TX_N: P1.15 ; also on sheet 10
USB2_TX_P: P1.13 ; also on sheet 10
USB2_VBUS: P1.1 ; also on sheet 10
USB_OC_LIMIT: R193.1 U41.8(IP)
USB_PWR_EN: R191.2 U41.5(EN) ; also on sheet 13
USBSD_VBUS: C182.2 C194.1 P21.1(VBUS) R169.2 R194.2
USBSDM_DN: L16.4 P21.2(D-)
USBSDM_DP: L16.3 P21.3(D+)
USBSERIAL_3V45: C140.1 C141.1 C144.1 R134.1 U24.5(VIO) U24.6(VDD) U25.7(VCCB)
USBSERIAL_DN: P3.2(D-) U24.4(DN) U26.6(IO4)
USBSERIAL_DP: P3.3(D+) U24.3(DP) U26.1(IO1)
USBSERIAL_nRST: R134.2 U24.9(RST#)
USBSERIALEN: R76.1 U25.6(OE)
V_SOM: C2.1 C3.1 C4.1 C5.1 C6.1 C7.1 C8.1 C9.1 C10.1 C11.1 C12.1 C13.1 C21.1 C340.1 C341.1 C342.1 C344.1 C345.1 C346.1 P1.11 P1.27 P1.43 P1.57 P1.69 P1.83 P2.9 P2.19 P2.29 P2.39 P2.57 P2.71 P2.87 ; also on sheet 11 12
N17460745: E3.2 R69.2 SW2.1 SW2.3
N18467226: D24.1(CATHODE) R264.2
N19824922: R194.1 U46.1(A)
N19824927: R201.1 U46.2(B)
N19825183: R172.2 U34.8(\\~{O}E)
N19910404: P6.P11(LED1_C) R101.1
N19910432: P6.P13(LED2_C) R133.1
N19936904: R329.1 U44.6(OE)
N19937445: R331.1 U45.6(OE)
N19977987: R257.1 R260.1
N19978151: P23.52(PERST#) R234.1 U7.4(OUT)
N19984730: Q6.6(D1) R90.1
N19984735: Q6.3(D2) R91.1
N19984752: DS4.CATHODE R90.2
N19984757: DS5.CATHODE R91.2
N19989907: R217.2 U42.8(\\~{O}E)

Not connected (* = marked no-connect by the designer): P1 17* 22* 35* 37* 55* 62* 95* 97* 99*; P2 51* 66* 75* 77*; P3 4(ID)* 10(NC1)* 11(NC2)*; P13 4* 6*; P21 4(ID)*; P22 14(NC)*; P23 6(LED1#)* 8(PCM_CLK/I2S_SCK(1.8V))* 9(SDIO_CLK)* 10(PCM_SYNC/I2S_WS(1.8V))* 11(SDIO_CMD)* 12(PCM_IN/I2S_SD_IN(1.8V))* 14(PCM_OUT/I2S_SD_OUT(1.8V))* 15(SDIO_D1)* 16(LED2#)* 17(SDIO_D2)* 20(UART_WAKE#)* 21(SDIO_WAKE#)* 22(UART_RX(1.8V))* 23(SDIO_RESET#)* 32(UART_TX(1.8V))* 34(UART_CTS(1.8V))* 36(UART_RTS(1.8V))* 38(RSVD/CLINK_RST)* 40(RSVD/CLINK_DATA)* 42(RSVD/CLINK_CLK)* 44(COEX3(1.8V))* 46(COEX2_RXD(1.8V))* 48(COEX1_TXD(1.8V))* 54(W_DIS2#)* 56(W_DIS1#)* 58(I2C_DATA)* 59(RSVD/PETP1)* 60(I2C_CLK)* 61(RSVD/PETN1)* 62(ALERT#)* 64(RSVD)* 65(RSVD/PERP1)* 66(UIM_SWP/RESET1#)* 67(RSVD/PERN1)* 68(UIM_PWRSNK/CLKREQ1#)* 70(UIM_PWRSRC/WAKE1#)* 71(RSVD/REFCLK1P)* 73(RSVD/REFCLK1N)*; U14 35(CLKOUT)*; U24 1(RI)* 10(NC)* 11(GPIO3)* 12(GPIO2)* 13(GPIO1)* 14(GPIO0)* 15(SUSPEND#)* 16(VPP)* 17(SUSPEND)* 18(CTS)* 19(RTS)* 22(DSR)* 23(DTR)* 24(DCD)*; U26 3(IO2)* 4(IO3)*; U27 4(IO3)*; U28 3(IO2)*; U41 1(FLG)*

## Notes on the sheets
sheet 1
- M.2 for WiFi module
- DNP
- User LEDs
sheet 2
- Carrier-board Ethernet PHY
- Power-on strap pins CFG
- RGMII Power Source
- CFG_EXT
- CFG_LDO[1:0]
- External 3.3V
- 1
- 00
- External 1.8V
- 1
- 10
- Internal 1.8V
- 0
- 10
- CFG_EXT
- DNP
- DNP
- CFG_LDO1
- CFG_LDO0
- CONFIG PINS
- Active low
- Active high
- Active low
- DNP
- DNP
- DNP
- PLLOFF
- TXDLY
- RXDLY
- DNP
- PHYADDRESS2
- DNP
- PHYADDRESS1
- PHYADDRESS0
- Carrier-board Ethernet
  connector
- PHY ADDRESS = [1,0,0]
- PHY support addresses from 00001 to 00111.
  PHY address 0 is a broadcast from the MAC
- PLLOFF: Pull-up to disable PLL @ ALDPS mode.
- Enable internal delays
- TX delay is enabled
  RX delay is enabled
sheet 3
- HDMI connector
- DDC level shifter
- # 100-Ohm diff pairs
- # 100-Ohm diff pairs
- HPD and CEC level shifter
- SILKSCREEN:
  HDMI 2.0
- Camera Edge Connector
- I2C level shifters
- CSI1
- CSI2
sheet 4
- LVDS connector
- LVDS panel back-light
- SPDIF_RX = PWM2_OUT
- DNP
- # 100-Ohm diff pairs
- # 100-Ohm diff pairs
- MIPI-DSI panel back-light
- Typical LED configuration: Two parallel chains of 6 serially connected LEDs
- MIPI-DSI connector
- DNP
- # 100-Ohm diff pairs
- Touch-screen
- # 100-Ohm diff pairs
sheet 5
- SBEV-UCMIMX8PLUS
- Page
- Description
- 01
- Index and Block Diagram
- 02
- SOM connectors
- 03
- Console and UCM Ethernet
- 04
- Carrier-board Ethernet
- 05
- USB #1 and SDP
- 06
- USB #2 and mini-PCIe
- 07
- LVDS and MPI-DSI
- 08
- HDMI and MIPI-CSI
- 09
- Audio codec
- UART, CAN, SPI, JTAG, EEPROM,
  GPIO exp
- 10
- 11
- M.2 for WiFi module
- 12
- Power
- 13
- Mechanical
- CH #
- I2C devices
- I2C3
- EEPROM, PCA9500, codec, touch,
- I2C5
- Camera
- I2C5
- Camera
sheet 6
- V-SOM capacitors
- Place close to SOM connectors
- main console
- Buttons
- I2C pull-up resistors
sheet 7
- Serial debug console
- UCM RX <--> CP2104 TX
  UCM RT <--> CP2104 RX
- SERIAL CONSOLE PORT
  (microUSB2.0 Type B)
  UART over USB
- A53 core debug
- O
- O
- SILKSCREEN:
  Serial Console USB to UART2
- UCM Ethernet connector
- Micro-SD socket (bootable)
- SILKSCREEN:
  ETH0
- SILKSCREEN:
  MicroSD (SD2)
- 100 Ohm
- 100 Ohm
- 100 Ohm
- 100 Ohm
sheet 8
- USB #1 SDP mux (USB2 signals only)
- USB #1 connector
- 90 ohm
- # 90-Ohm differential pairs
- # 90-Ohm differential pairs
- USB #1 M.2 mux (USB2 signals only)
- SDP connector
- # 90-Ohm diff pairs
- # 90-Ohm differential pairs
- Serial Download mode
  (microUSB2.0 Type B)
- E4 operation
  Open:       for M.2 socket
  Close:      for USB conn. J3
- USB power
- USB VBUS
- Cur. limit =
  2.1 A/ 3ports
